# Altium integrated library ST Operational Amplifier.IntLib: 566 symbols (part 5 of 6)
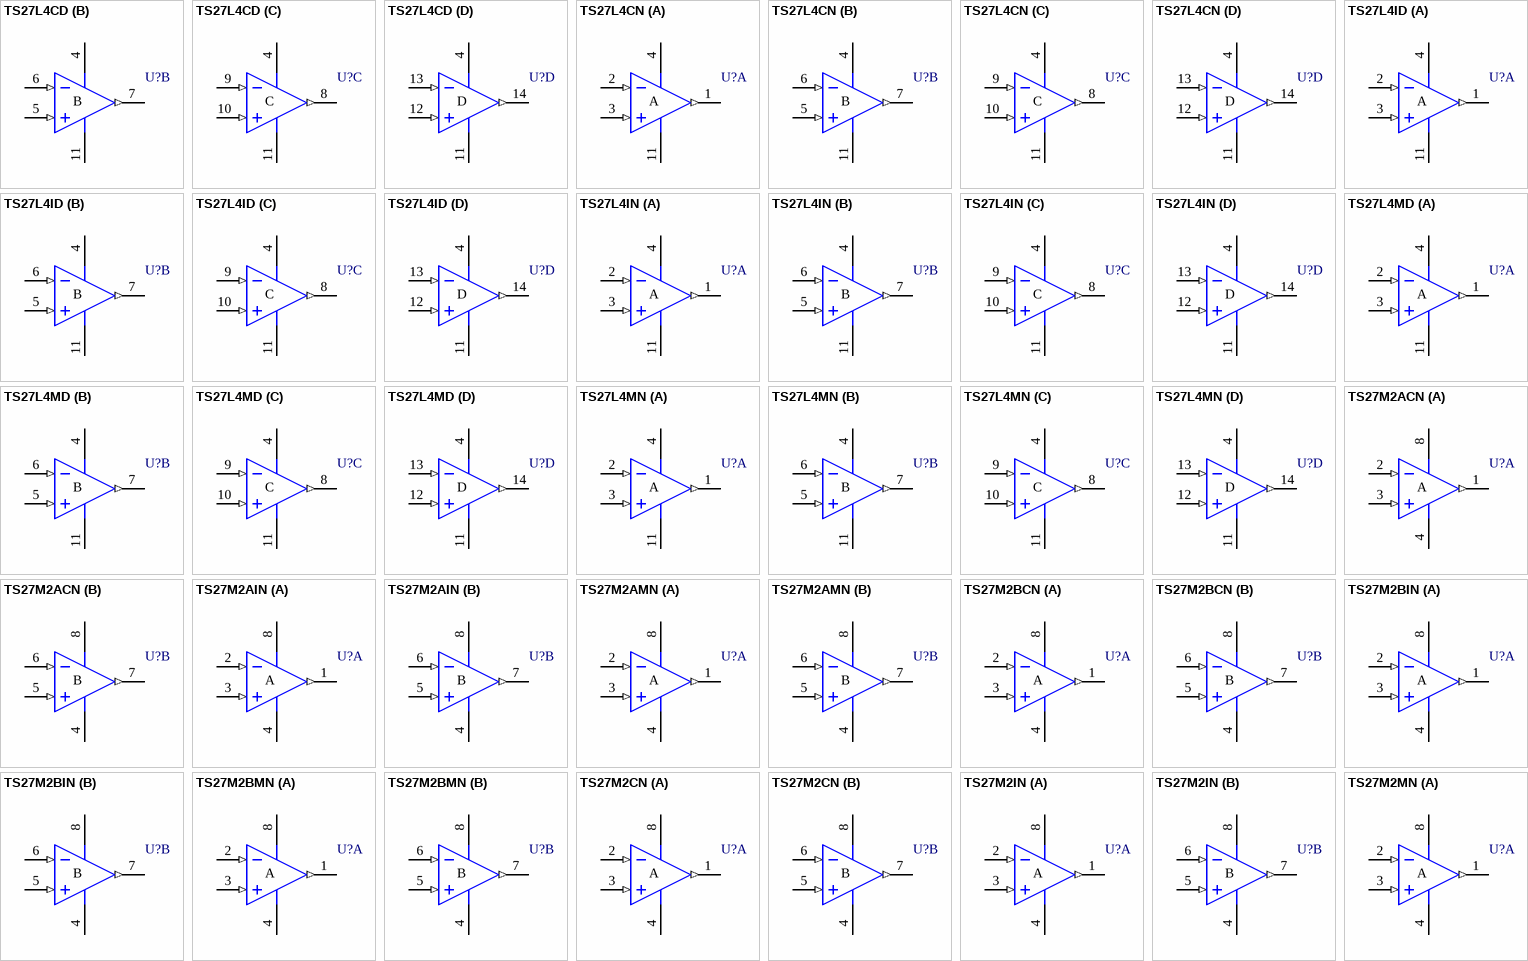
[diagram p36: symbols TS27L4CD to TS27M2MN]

## TS27L4ID
designator U?
Very Low-Power CMOS Quad Operational Amplifier
footprint SO14_N (SOIC, 14-Leads, Body 8.7x3.9mm, Pitch 1.27mm, IPC Medium Density)
footprint SO14_L (SOIC, 14-Leads, Body 8.7x3.9mm, Pitch 1.27mm, IPC High Density)
footprint SO14_M (SOIC, 14-Leads, Body 8.7x3.9mm, Pitch 1.27mm, IPC Low Density)
3D model SO14 (14-Pin Small Outline Integrated Circuit 1.27 mm Pitch)
pins on every part: 4 V+ (power), 11 V- (power)
part A pins: 1 OUT (out), 2 IN- (in), 3 IN+ (in)
part B pins: 5 IN+ (in), 6 IN- (in), 7 OUT (out)
part C pins: 8 OUT (out), 9 IN- (in), 10 IN+ (in)
part D pins: 12 IN+ (in), 13 IN- (in), 14 OUT (out)

## TS27L4IN
designator U?
Very Low-Power CMOS Quad Operational Amplifier
footprint DIP14 (DIP; 14 Leads; Row Spacing 7.62 mm; Pitch 2.54 mm)
3D model DIP14 (DIP; 14 Leads; Row Spacing 7.62 mm; Pitch 2.54 mm)
pins on every part: 4 V+ (power), 11 V- (power)
part A pins: 1 OUT (out), 2 IN- (in), 3 IN+ (in)
part B pins: 5 IN+ (in), 6 IN- (in), 7 OUT (out)
part C pins: 8 OUT (out), 9 IN- (in), 10 IN+ (in)
part D pins: 12 IN+ (in), 13 IN- (in), 14 OUT (out)

## TS27L4MD
designator U?
Very Low-Power CMOS Quad Operational Amplifier
footprint SO14_N (SOIC, 14-Leads, Body 8.7x3.9mm, Pitch 1.27mm, IPC Medium Density)
footprint SO14_L (SOIC, 14-Leads, Body 8.7x3.9mm, Pitch 1.27mm, IPC High Density)
footprint SO14_M (SOIC, 14-Leads, Body 8.7x3.9mm, Pitch 1.27mm, IPC Low Density)
3D model SO14 (14-Pin Small Outline Integrated Circuit 1.27 mm Pitch)
pins on every part: 4 V+ (power), 11 V- (power)
part A pins: 1 OUT (out), 2 IN- (in), 3 IN+ (in)
part B pins: 5 IN+ (in), 6 IN- (in), 7 OUT (out)
part C pins: 8 OUT (out), 9 IN- (in), 10 IN+ (in)
part D pins: 12 IN+ (in), 13 IN- (in), 14 OUT (out)

## TS27L4MN
designator U?
Very Low-Power CMOS Quad Operational Amplifier
footprint DIP14 (DIP; 14 Leads; Row Spacing 7.62 mm; Pitch 2.54 mm)
3D model DIP14 (DIP; 14 Leads; Row Spacing 7.62 mm; Pitch 2.54 mm)
pins on every part: 4 V+ (power), 11 V- (power)
part A pins: 1 OUT (out), 2 IN- (in), 3 IN+ (in)
part B pins: 5 IN+ (in), 6 IN- (in), 7 OUT (out)
part C pins: 8 OUT (out), 9 IN- (in), 10 IN+ (in)
part D pins: 12 IN+ (in), 13 IN- (in), 14 OUT (out)

## TS27M2ACN
designator U?
Low-Power CMOS Dual Operational Amplifier
footprint DIP8 (DIP; 8 Leads; Row Spacing 7.62 mm; Pitch 2.54 mm)
3D model DIP8 (DIP; 8 Leads; Row Spacing 7.62 mm; Pitch 2.54 mm)
pins on every part: 4 V- (power), 8 V+ (power)
part A pins: 1 OUT (out), 2 IN- (in), 3 IN+ (in)
part B pins: 5 IN+ (in), 6 IN- (in), 7 OUT (out)

## TS27M2AIN
designator U?
Low-Power CMOS Dual Operational Amplifier
footprint DIP8 (DIP; 8 Leads; Row Spacing 7.62 mm; Pitch 2.54 mm)
3D model DIP8 (DIP; 8 Leads; Row Spacing 7.62 mm; Pitch 2.54 mm)
pins on every part: 4 V- (power), 8 V+ (power)
part A pins: 1 OUT (out), 2 IN- (in), 3 IN+ (in)
part B pins: 5 IN+ (in), 6 IN- (in), 7 OUT (out)

## TS27M2AMN
designator U?
Low-Power CMOS Dual Operational Amplifier
footprint DIP8 (DIP; 8 Leads; Row Spacing 7.62 mm; Pitch 2.54 mm)
3D model DIP8 (DIP; 8 Leads; Row Spacing 7.62 mm; Pitch 2.54 mm)
pins on every part: 4 V- (power), 8 V+ (power)
part A pins: 1 OUT (out), 2 IN- (in), 3 IN+ (in)
part B pins: 5 IN+ (in), 6 IN- (in), 7 OUT (out)

## TS27M2BCN
designator U?
Low-Power CMOS Dual Operational Amplifier
footprint DIP8 (DIP; 8 Leads; Row Spacing 7.62 mm; Pitch 2.54 mm)
3D model DIP8 (DIP; 8 Leads; Row Spacing 7.62 mm; Pitch 2.54 mm)
pins on every part: 4 V- (power), 8 V+ (power)
part A pins: 1 OUT (out), 2 IN- (in), 3 IN+ (in)
part B pins: 5 IN+ (in), 6 IN- (in), 7 OUT (out)

## TS27M2BIN
designator U?
Low-Power CMOS Dual Operational Amplifier
footprint DIP8 (DIP; 8 Leads; Row Spacing 7.62 mm; Pitch 2.54 mm)
3D model DIP8 (DIP; 8 Leads; Row Spacing 7.62 mm; Pitch 2.54 mm)
pins on every part: 4 V- (power), 8 V+ (power)
part A pins: 1 OUT (out), 2 IN- (in), 3 IN+ (in)
part B pins: 5 IN+ (in), 6 IN- (in), 7 OUT (out)

## TS27M2BMN
designator U?
Low-Power CMOS Dual Operational Amplifier
footprint DIP8 (DIP; 8 Leads; Row Spacing 7.62 mm; Pitch 2.54 mm)
3D model DIP8 (DIP; 8 Leads; Row Spacing 7.62 mm; Pitch 2.54 mm)
pins on every part: 4 V- (power), 8 V+ (power)
part A pins: 1 OUT (out), 2 IN- (in), 3 IN+ (in)
part B pins: 5 IN+ (in), 6 IN- (in), 7 OUT (out)

## TS27M2CN
designator U?
Low-Power CMOS Dual Operational Amplifier
footprint DIP8 (DIP; 8 Leads; Row Spacing 7.62 mm; Pitch 2.54 mm)
3D model DIP8 (DIP; 8 Leads; Row Spacing 7.62 mm; Pitch 2.54 mm)
pins on every part: 4 V- (power), 8 V+ (power)
part A pins: 1 OUT (out), 2 IN- (in), 3 IN+ (in)
part B pins: 5 IN+ (in), 6 IN- (in), 7 OUT (out)

## TS27M2IN
designator U?
Low-Power CMOS Dual Operational Amplifier
footprint DIP8 (DIP; 8 Leads; Row Spacing 7.62 mm; Pitch 2.54 mm)
3D model DIP8 (DIP; 8 Leads; Row Spacing 7.62 mm; Pitch 2.54 mm)
pins on every part: 4 V- (power), 8 V+ (power)
part A pins: 1 OUT (out), 2 IN- (in), 3 IN+ (in)
part B pins: 5 IN+ (in), 6 IN- (in), 7 OUT (out)

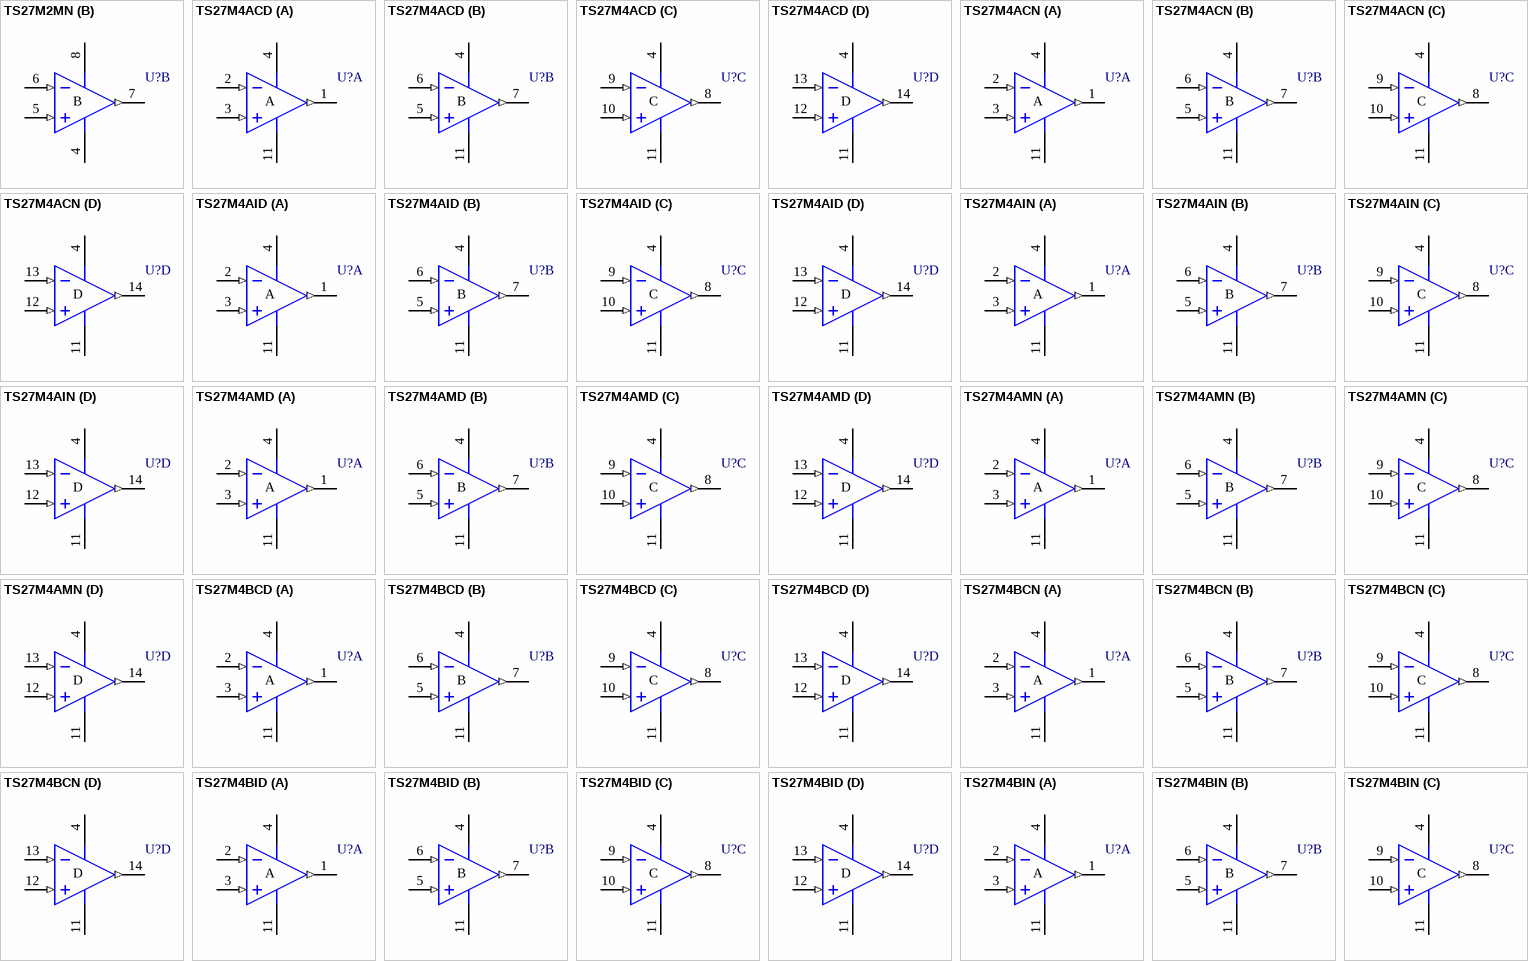
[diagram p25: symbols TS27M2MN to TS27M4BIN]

## TS27M2MN
designator U?
Low-Power CMOS Dual Operational Amplifier
footprint DIP8 (DIP; 8 Leads; Row Spacing 7.62 mm; Pitch 2.54 mm)
3D model DIP8 (DIP; 8 Leads; Row Spacing 7.62 mm; Pitch 2.54 mm)
pins on every part: 4 V- (power), 8 V+ (power)
part A pins: 1 OUT (out), 2 IN- (in), 3 IN+ (in)
part B pins: 5 IN+ (in), 6 IN- (in), 7 OUT (out)

## TS27M4ACD
designator U?
Low-Power CMOS Quad Operational Amplifier
footprint SO14_N (SOIC, 14-Leads, Body 8.7x3.9mm, Pitch 1.27mm, IPC Medium Density)
footprint SO14_L (SOIC, 14-Leads, Body 8.7x3.9mm, Pitch 1.27mm, IPC High Density)
footprint SO14_M (SOIC, 14-Leads, Body 8.7x3.9mm, Pitch 1.27mm, IPC Low Density)
3D model SO14 (14-Pin Small Outline Integrated Circuit 1.27 mm Pitch)
pins on every part: 4 V+ (power), 11 V- (power)
part A pins: 1 OUT (out), 2 IN- (in), 3 IN+ (in)
part B pins: 5 IN+ (in), 6 IN- (in), 7 OUT (out)
part C pins: 8 OUT (out), 9 IN- (in), 10 IN+ (in)
part D pins: 12 IN+ (in), 13 IN- (in), 14 OUT (out)

## TS27M4ACN
designator U?
Low-Power CMOS Quad Operational Amplifier
footprint DIP14 (DIP; 14 Leads; Row Spacing 7.62 mm; Pitch 2.54 mm)
3D model DIP14 (DIP; 14 Leads; Row Spacing 7.62 mm; Pitch 2.54 mm)
pins on every part: 4 V+ (power), 11 V- (power)
part A pins: 1 OUT (out), 2 IN- (in), 3 IN+ (in)
part B pins: 5 IN+ (in), 6 IN- (in), 7 OUT (out)
part C pins: 8 OUT (out), 9 IN- (in), 10 IN+ (in)
part D pins: 12 IN+ (in), 13 IN- (in), 14 OUT (out)

## TS27M4AID
designator U?
Low-Power CMOS Quad Operational Amplifier
footprint SO14_N (SOIC, 14-Leads, Body 8.7x3.9mm, Pitch 1.27mm, IPC Medium Density)
footprint SO14_L (SOIC, 14-Leads, Body 8.7x3.9mm, Pitch 1.27mm, IPC High Density)
footprint SO14_M (SOIC, 14-Leads, Body 8.7x3.9mm, Pitch 1.27mm, IPC Low Density)
3D model SO14 (14-Pin Small Outline Integrated Circuit 1.27 mm Pitch)
pins on every part: 4 V+ (power), 11 V- (power)
part A pins: 1 OUT (out), 2 IN- (in), 3 IN+ (in)
part B pins: 5 IN+ (in), 6 IN- (in), 7 OUT (out)
part C pins: 8 OUT (out), 9 IN- (in), 10 IN+ (in)
part D pins: 12 IN+ (in), 13 IN- (in), 14 OUT (out)

## TS27M4AIN
designator U?
Low-Power CMOS Quad Operational Amplifier
footprint DIP14 (DIP; 14 Leads; Row Spacing 7.62 mm; Pitch 2.54 mm)
3D model DIP14 (DIP; 14 Leads; Row Spacing 7.62 mm; Pitch 2.54 mm)
pins on every part: 4 V+ (power), 11 V- (power)
part A pins: 1 OUT (out), 2 IN- (in), 3 IN+ (in)
part B pins: 5 IN+ (in), 6 IN- (in), 7 OUT (out)
part C pins: 8 OUT (out), 9 IN- (in), 10 IN+ (in)
part D pins: 12 IN+ (in), 13 IN- (in), 14 OUT (out)

## TS27M4AMD
designator U?
Low-Power CMOS Quad Operational Amplifier
footprint SO14_N (SOIC, 14-Leads, Body 8.7x3.9mm, Pitch 1.27mm, IPC Medium Density)
footprint SO14_L (SOIC, 14-Leads, Body 8.7x3.9mm, Pitch 1.27mm, IPC High Density)
footprint SO14_M (SOIC, 14-Leads, Body 8.7x3.9mm, Pitch 1.27mm, IPC Low Density)
3D model SO14 (14-Pin Small Outline Integrated Circuit 1.27 mm Pitch)
pins on every part: 4 V+ (power), 11 V- (power)
part A pins: 1 OUT (out), 2 IN- (in), 3 IN+ (in)
part B pins: 5 IN+ (in), 6 IN- (in), 7 OUT (out)
part C pins: 8 OUT (out), 9 IN- (in), 10 IN+ (in)
part D pins: 12 IN+ (in), 13 IN- (in), 14 OUT (out)

## TS27M4AMN
designator U?
Low-Power CMOS Quad Operational Amplifier
footprint DIP14 (DIP; 14 Leads; Row Spacing 7.62 mm; Pitch 2.54 mm)
3D model DIP14 (DIP; 14 Leads; Row Spacing 7.62 mm; Pitch 2.54 mm)
pins on every part: 4 V+ (power), 11 V- (power)
part A pins: 1 OUT (out), 2 IN- (in), 3 IN+ (in)
part B pins: 5 IN+ (in), 6 IN- (in), 7 OUT (out)
part C pins: 8 OUT (out), 9 IN- (in), 10 IN+ (in)
part D pins: 12 IN+ (in), 13 IN- (in), 14 OUT (out)

## TS27M4BCD
designator U?
Low-Power CMOS Quad Operational Amplifier
footprint SO14_N (SOIC, 14-Leads, Body 8.7x3.9mm, Pitch 1.27mm, IPC Medium Density)
footprint SO14_L (SOIC, 14-Leads, Body 8.7x3.9mm, Pitch 1.27mm, IPC High Density)
footprint SO14_M (SOIC, 14-Leads, Body 8.7x3.9mm, Pitch 1.27mm, IPC Low Density)
3D model SO14 (14-Pin Small Outline Integrated Circuit 1.27 mm Pitch)
pins on every part: 4 V+ (power), 11 V- (power)
part A pins: 1 OUT (out), 2 IN- (in), 3 IN+ (in)
part B pins: 5 IN+ (in), 6 IN- (in), 7 OUT (out)
part C pins: 8 OUT (out), 9 IN- (in), 10 IN+ (in)
part D pins: 12 IN+ (in), 13 IN- (in), 14 OUT (out)

## TS27M4BCN
designator U?
Low-Power CMOS Quad Operational Amplifier
footprint DIP14 (DIP; 14 Leads; Row Spacing 7.62 mm; Pitch 2.54 mm)
3D model DIP14 (DIP; 14 Leads; Row Spacing 7.62 mm; Pitch 2.54 mm)
pins on every part: 4 V+ (power), 11 V- (power)
part A pins: 1 OUT (out), 2 IN- (in), 3 IN+ (in)
part B pins: 5 IN+ (in), 6 IN- (in), 7 OUT (out)
part C pins: 8 OUT (out), 9 IN- (in), 10 IN+ (in)
part D pins: 12 IN+ (in), 13 IN- (in), 14 OUT (out)

## TS27M4BID
designator U?
Low-Power CMOS Quad Operational Amplifier
footprint SO14_N (SOIC, 14-Leads, Body 8.7x3.9mm, Pitch 1.27mm, IPC Medium Density)
footprint SO14_L (SOIC, 14-Leads, Body 8.7x3.9mm, Pitch 1.27mm, IPC High Density)
footprint SO14_M (SOIC, 14-Leads, Body 8.7x3.9mm, Pitch 1.27mm, IPC Low Density)
3D model SO14 (14-Pin Small Outline Integrated Circuit 1.27 mm Pitch)
pins on every part: 4 V+ (power), 11 V- (power)
part A pins: 1 OUT (out), 2 IN- (in), 3 IN+ (in)
part B pins: 5 IN+ (in), 6 IN- (in), 7 OUT (out)
part C pins: 8 OUT (out), 9 IN- (in), 10 IN+ (in)
part D pins: 12 IN+ (in), 13 IN- (in), 14 OUT (out)

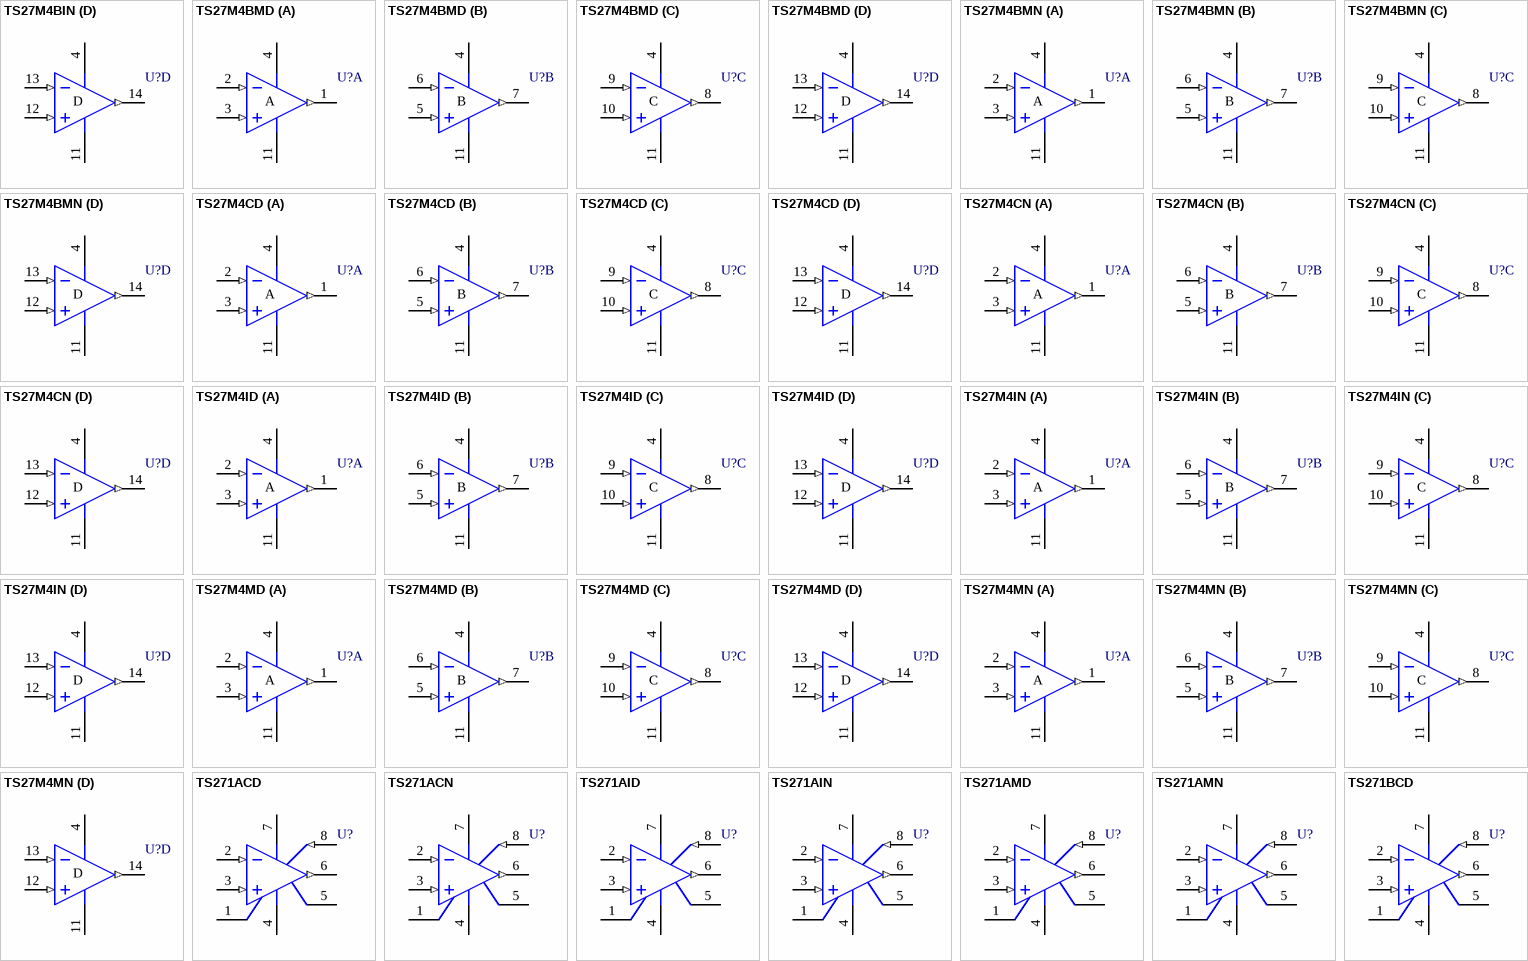
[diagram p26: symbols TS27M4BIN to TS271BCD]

## TS27M4BIN
designator U?
Low-Power CMOS Quad Operational Amplifier
footprint DIP14 (DIP; 14 Leads; Row Spacing 7.62 mm; Pitch 2.54 mm)
3D model DIP14 (DIP; 14 Leads; Row Spacing 7.62 mm; Pitch 2.54 mm)
pins on every part: 4 V+ (power), 11 V- (power)
part A pins: 1 OUT (out), 2 IN- (in), 3 IN+ (in)
part B pins: 5 IN+ (in), 6 IN- (in), 7 OUT (out)
part C pins: 8 OUT (out), 9 IN- (in), 10 IN+ (in)
part D pins: 12 IN+ (in), 13 IN- (in), 14 OUT (out)

## TS27M4BMD
designator U?
Low-Power CMOS Quad Operational Amplifier
footprint SO14_N (SOIC, 14-Leads, Body 8.7x3.9mm, Pitch 1.27mm, IPC Medium Density)
footprint SO14_L (SOIC, 14-Leads, Body 8.7x3.9mm, Pitch 1.27mm, IPC High Density)
footprint SO14_M (SOIC, 14-Leads, Body 8.7x3.9mm, Pitch 1.27mm, IPC Low Density)
3D model SO14 (14-Pin Small Outline Integrated Circuit 1.27 mm Pitch)
pins on every part: 4 V+ (power), 11 V- (power)
part A pins: 1 OUT (out), 2 IN- (in), 3 IN+ (in)
part B pins: 5 IN+ (in), 6 IN- (in), 7 OUT (out)
part C pins: 8 OUT (out), 9 IN- (in), 10 IN+ (in)
part D pins: 12 IN+ (in), 13 IN- (in), 14 OUT (out)

## TS27M4BMN
designator U?
Low-Power CMOS Quad Operational Amplifier
footprint DIP14 (DIP; 14 Leads; Row Spacing 7.62 mm; Pitch 2.54 mm)
3D model DIP14 (DIP; 14 Leads; Row Spacing 7.62 mm; Pitch 2.54 mm)
pins on every part: 4 V+ (power), 11 V- (power)
part A pins: 1 OUT (out), 2 IN- (in), 3 IN+ (in)
part B pins: 5 IN+ (in), 6 IN- (in), 7 OUT (out)
part C pins: 8 OUT (out), 9 IN- (in), 10 IN+ (in)
part D pins: 12 IN+ (in), 13 IN- (in), 14 OUT (out)

## TS27M4CD
designator U?
Low-Power CMOS Quad Operational Amplifier
footprint SO14_N (SOIC, 14-Leads, Body 8.7x3.9mm, Pitch 1.27mm, IPC Medium Density)
footprint SO14_L (SOIC, 14-Leads, Body 8.7x3.9mm, Pitch 1.27mm, IPC High Density)
footprint SO14_M (SOIC, 14-Leads, Body 8.7x3.9mm, Pitch 1.27mm, IPC Low Density)
3D model SO14 (14-Pin Small Outline Integrated Circuit 1.27 mm Pitch)
pins on every part: 4 V+ (power), 11 V- (power)
part A pins: 1 OUT (out), 2 IN- (in), 3 IN+ (in)
part B pins: 5 IN+ (in), 6 IN- (in), 7 OUT (out)
part C pins: 8 OUT (out), 9 IN- (in), 10 IN+ (in)
part D pins: 12 IN+ (in), 13 IN- (in), 14 OUT (out)

## TS27M4CN
designator U?
Low-Power CMOS Quad Operational Amplifier
footprint DIP14 (DIP; 14 Leads; Row Spacing 7.62 mm; Pitch 2.54 mm)
3D model DIP14 (DIP; 14 Leads; Row Spacing 7.62 mm; Pitch 2.54 mm)
pins on every part: 4 V+ (power), 11 V- (power)
part A pins: 1 OUT (out), 2 IN- (in), 3 IN+ (in)
part B pins: 5 IN+ (in), 6 IN- (in), 7 OUT (out)
part C pins: 8 OUT (out), 9 IN- (in), 10 IN+ (in)
part D pins: 12 IN+ (in), 13 IN- (in), 14 OUT (out)

## TS27M4ID
designator U?
Low-Power CMOS Quad Operational Amplifier
footprint SO14_N (SOIC, 14-Leads, Body 8.7x3.9mm, Pitch 1.27mm, IPC Medium Density)
footprint SO14_L (SOIC, 14-Leads, Body 8.7x3.9mm, Pitch 1.27mm, IPC High Density)
footprint SO14_M (SOIC, 14-Leads, Body 8.7x3.9mm, Pitch 1.27mm, IPC Low Density)
3D model SO14 (14-Pin Small Outline Integrated Circuit 1.27 mm Pitch)
pins on every part: 4 V+ (power), 11 V- (power)
part A pins: 1 OUT (out), 2 IN- (in), 3 IN+ (in)
part B pins: 5 IN+ (in), 6 IN- (in), 7 OUT (out)
part C pins: 8 OUT (out), 9 IN- (in), 10 IN+ (in)
part D pins: 12 IN+ (in), 13 IN- (in), 14 OUT (out)

## TS27M4IN
designator U?
Low-Power CMOS Quad Operational Amplifier
footprint DIP14 (DIP; 14 Leads; Row Spacing 7.62 mm; Pitch 2.54 mm)
3D model DIP14 (DIP; 14 Leads; Row Spacing 7.62 mm; Pitch 2.54 mm)
pins on every part: 4 V+ (power), 11 V- (power)
part A pins: 1 OUT (out), 2 IN- (in), 3 IN+ (in)
part B pins: 5 IN+ (in), 6 IN- (in), 7 OUT (out)
part C pins: 8 OUT (out), 9 IN- (in), 10 IN+ (in)
part D pins: 12 IN+ (in), 13 IN- (in), 14 OUT (out)

## TS27M4MD
designator U?
Low-Power CMOS Quad Operational Amplifier
footprint SO14_N (SOIC, 14-Leads, Body 8.7x3.9mm, Pitch 1.27mm, IPC Medium Density)
footprint SO14_L (SOIC, 14-Leads, Body 8.7x3.9mm, Pitch 1.27mm, IPC High Density)
footprint SO14_M (SOIC, 14-Leads, Body 8.7x3.9mm, Pitch 1.27mm, IPC Low Density)
3D model SO14 (14-Pin Small Outline Integrated Circuit 1.27 mm Pitch)
pins on every part: 4 V+ (power), 11 V- (power)
part A pins: 1 OUT (out), 2 IN- (in), 3 IN+ (in)
part B pins: 5 IN+ (in), 6 IN- (in), 7 OUT (out)
part C pins: 8 OUT (out), 9 IN- (in), 10 IN+ (in)
part D pins: 12 IN+ (in), 13 IN- (in), 14 OUT (out)

## TS27M4MN
designator U?
Low-Power CMOS Quad Operational Amplifier
footprint DIP14 (DIP; 14 Leads; Row Spacing 7.62 mm; Pitch 2.54 mm)
3D model DIP14 (DIP; 14 Leads; Row Spacing 7.62 mm; Pitch 2.54 mm)
pins on every part: 4 V+ (power), 11 V- (power)
part A pins: 1 OUT (out), 2 IN- (in), 3 IN+ (in)
part B pins: 5 IN+ (in), 6 IN- (in), 7 OUT (out)
part C pins: 8 OUT (out), 9 IN- (in), 10 IN+ (in)
part D pins: 12 IN+ (in), 13 IN- (in), 14 OUT (out)

## TS271ACD
designator U?
Programmable CMOS Single Operational Amplifier
footprint SO8_N (SOIC, 8-Leads, Body 4.9x3.9mm, Pitch 1.27mm, IPC Medium Density)
footprint SO8_L (SOIC, 8-Leads, Body 4.9x3.9mm, Pitch 1.27mm, IPC High Density)
footprint SO8_M (SOIC, 8-Leads, Body 4.9x3.9mm, Pitch 1.27mm, IPC Low Density)
3D model SO8 (8-Pin Small Outline Integrated Circuit 1.27 mm Pitch)
pins: 1 OS NULL1, 2 IN- (in), 3 IN+ (in), 4 V- (power), 5 OS NULL2, 6 OUT (out), 7 V+ (power), 8 ISET (in)

## TS271ACN
designator U?
Programmable CMOS Single Operational Amplifier
footprint DIP8 (DIP; 8 Leads; Row Spacing 7.62 mm; Pitch 2.54 mm)
3D model DIP8 (DIP; 8 Leads; Row Spacing 7.62 mm; Pitch 2.54 mm)
pins: 1 OS NULL1, 2 IN- (in), 3 IN+ (in), 4 V- (power), 5 OS NULL2, 6 OUT (out), 7 V+ (power), 8 ISET (in)

## TS271AID
designator U?
Programmable CMOS Single Operational Amplifier
footprint SO8_N (SOIC, 8-Leads, Body 4.9x3.9mm, Pitch 1.27mm, IPC Medium Density)
footprint SO8_L (SOIC, 8-Leads, Body 4.9x3.9mm, Pitch 1.27mm, IPC High Density)
footprint SO8_M (SOIC, 8-Leads, Body 4.9x3.9mm, Pitch 1.27mm, IPC Low Density)
3D model SO8 (8-Pin Small Outline Integrated Circuit 1.27 mm Pitch)
pins: 1 OS NULL1, 2 IN- (in), 3 IN+ (in), 4 V- (power), 5 OS NULL2, 6 OUT (out), 7 V+ (power), 8 ISET (in)

## TS271AIN
designator U?
Programmable CMOS Single Operational Amplifier
footprint DIP8 (DIP; 8 Leads; Row Spacing 7.62 mm; Pitch 2.54 mm)
3D model DIP8 (DIP; 8 Leads; Row Spacing 7.62 mm; Pitch 2.54 mm)
pins: 1 OS NULL1, 2 IN- (in), 3 IN+ (in), 4 V- (power), 5 OS NULL2, 6 OUT (out), 7 V+ (power), 8 ISET (in)

## TS271AMD
designator U?
Programmable CMOS Single Operational Amplifier
footprint SO8_N (SOIC, 8-Leads, Body 4.9x3.9mm, Pitch 1.27mm, IPC Medium Density)
footprint SO8_L (SOIC, 8-Leads, Body 4.9x3.9mm, Pitch 1.27mm, IPC High Density)
footprint SO8_M (SOIC, 8-Leads, Body 4.9x3.9mm, Pitch 1.27mm, IPC Low Density)
3D model SO8 (8-Pin Small Outline Integrated Circuit 1.27 mm Pitch)
pins: 1 OS NULL1, 2 IN- (in), 3 IN+ (in), 4 V- (power), 5 OS NULL2, 6 OUT (out), 7 V+ (power), 8 ISET (in)

## TS271AMN
designator U?
Programmable CMOS Single Operational Amplifier
footprint DIP8 (DIP; 8 Leads; Row Spacing 7.62 mm; Pitch 2.54 mm)
3D model DIP8 (DIP; 8 Leads; Row Spacing 7.62 mm; Pitch 2.54 mm)
pins: 1 OS NULL1, 2 IN- (in), 3 IN+ (in), 4 V- (power), 5 OS NULL2, 6 OUT (out), 7 V+ (power), 8 ISET (in)

## TS271BCD
designator U?
Programmable CMOS Single Operational Amplifier
footprint SO8_N (SOIC, 8-Leads, Body 4.9x3.9mm, Pitch 1.27mm, IPC Medium Density)
footprint SO8_L (SOIC, 8-Leads, Body 4.9x3.9mm, Pitch 1.27mm, IPC High Density)
footprint SO8_M (SOIC, 8-Leads, Body 4.9x3.9mm, Pitch 1.27mm, IPC Low Density)
3D model SO8 (8-Pin Small Outline Integrated Circuit 1.27 mm Pitch)
pins: 1 OS NULL1, 2 IN- (in), 3 IN+ (in), 4 V- (power), 5 OS NULL2, 6 OUT (out), 7 V+ (power), 8 ISET (in)

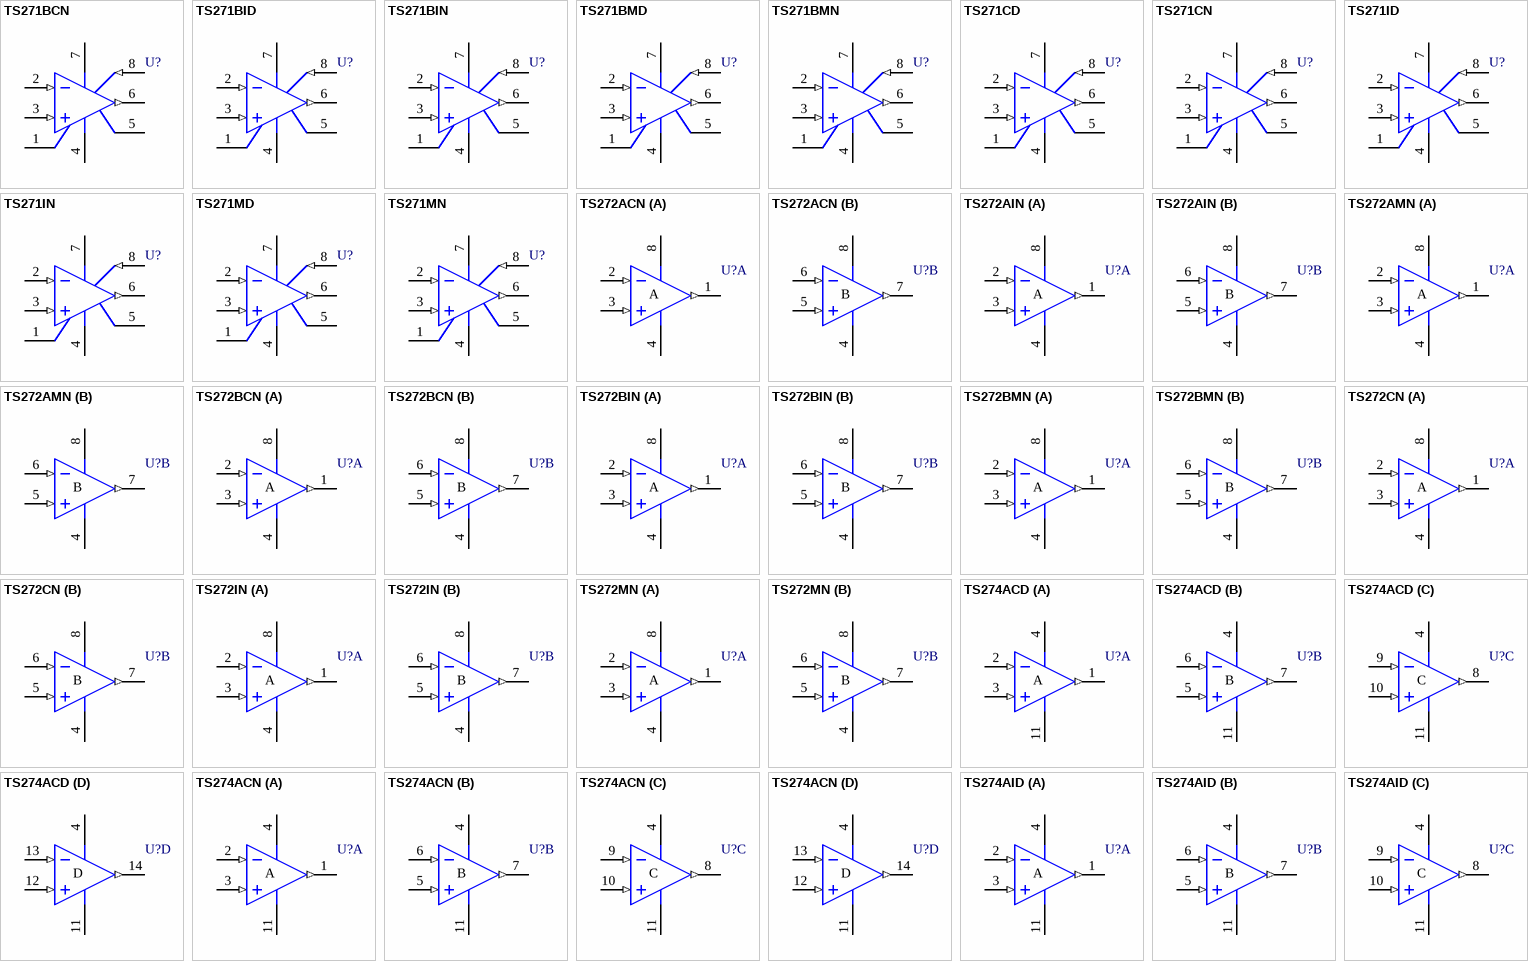
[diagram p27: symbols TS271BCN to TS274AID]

## TS271BCN
designator U?
Programmable CMOS Single Operational Amplifier
footprint DIP8 (DIP; 8 Leads; Row Spacing 7.62 mm; Pitch 2.54 mm)
3D model DIP8 (DIP; 8 Leads; Row Spacing 7.62 mm; Pitch 2.54 mm)
pins: 1 OS NULL1, 2 IN- (in), 3 IN+ (in), 4 V- (power), 5 OS NULL2, 6 OUT (out), 7 V+ (power), 8 ISET (in)

## TS271BID
designator U?
Programmable CMOS Single Operational Amplifier
footprint SO8_N (SOIC, 8-Leads, Body 4.9x3.9mm, Pitch 1.27mm, IPC Medium Density)
footprint SO8_L (SOIC, 8-Leads, Body 4.9x3.9mm, Pitch 1.27mm, IPC High Density)
footprint SO8_M (SOIC, 8-Leads, Body 4.9x3.9mm, Pitch 1.27mm, IPC Low Density)
3D model SO8 (8-Pin Small Outline Integrated Circuit 1.27 mm Pitch)
pins: 1 OS NULL1, 2 IN- (in), 3 IN+ (in), 4 V- (power), 5 OS NULL2, 6 OUT (out), 7 V+ (power), 8 ISET (in)

## TS271BIN
designator U?
Programmable CMOS Single Operational Amplifier
footprint DIP8 (DIP; 8 Leads; Row Spacing 7.62 mm; Pitch 2.54 mm)
3D model DIP8 (DIP; 8 Leads; Row Spacing 7.62 mm; Pitch 2.54 mm)
pins: 1 OS NULL1, 2 IN- (in), 3 IN+ (in), 4 V- (power), 5 OS NULL2, 6 OUT (out), 7 V+ (power), 8 ISET (in)

## TS271BMD
designator U?
Programmable CMOS Single Operational Amplifier
footprint SO8_N (SOIC, 8-Leads, Body 4.9x3.9mm, Pitch 1.27mm, IPC Medium Density)
footprint SO8_L (SOIC, 8-Leads, Body 4.9x3.9mm, Pitch 1.27mm, IPC High Density)
footprint SO8_M (SOIC, 8-Leads, Body 4.9x3.9mm, Pitch 1.27mm, IPC Low Density)
3D model SO8 (8-Pin Small Outline Integrated Circuit 1.27 mm Pitch)
pins: 1 OS NULL1, 2 IN- (in), 3 IN+ (in), 4 V- (power), 5 OS NULL2, 6 OUT (out), 7 V+ (power), 8 ISET (in)

## TS271BMN
designator U?
Programmable CMOS Single Operational Amplifier
footprint DIP8 (DIP; 8 Leads; Row Spacing 7.62 mm; Pitch 2.54 mm)
3D model DIP8 (DIP; 8 Leads; Row Spacing 7.62 mm; Pitch 2.54 mm)
pins: 1 OS NULL1, 2 IN- (in), 3 IN+ (in), 4 V- (power), 5 OS NULL2, 6 OUT (out), 7 V+ (power), 8 ISET (in)

## TS271CD
designator U?
Programmable CMOS Single Operational Amplifier
footprint SO8_N (SOIC, 8-Leads, Body 4.9x3.9mm, Pitch 1.27mm, IPC Medium Density)
footprint SO8_L (SOIC, 8-Leads, Body 4.9x3.9mm, Pitch 1.27mm, IPC High Density)
footprint SO8_M (SOIC, 8-Leads, Body 4.9x3.9mm, Pitch 1.27mm, IPC Low Density)
3D model SO8 (8-Pin Small Outline Integrated Circuit 1.27 mm Pitch)
pins: 1 OS NULL1, 2 IN- (in), 3 IN+ (in), 4 V- (power), 5 OS NULL2, 6 OUT (out), 7 V+ (power), 8 ISET (in)

## TS271CN
designator U?
Programmable CMOS Single Operational Amplifier
footprint DIP8 (DIP; 8 Leads; Row Spacing 7.62 mm; Pitch 2.54 mm)
3D model DIP8 (DIP; 8 Leads; Row Spacing 7.62 mm; Pitch 2.54 mm)
pins: 1 OS NULL1, 2 IN- (in), 3 IN+ (in), 4 V- (power), 5 OS NULL2, 6 OUT (out), 7 V+ (power), 8 ISET (in)

## TS271ID
designator U?
Programmable CMOS Single Operational Amplifier
footprint SO8_N (SOIC, 8-Leads, Body 4.9x3.9mm, Pitch 1.27mm, IPC Medium Density)
footprint SO8_L (SOIC, 8-Leads, Body 4.9x3.9mm, Pitch 1.27mm, IPC High Density)
footprint SO8_M (SOIC, 8-Leads, Body 4.9x3.9mm, Pitch 1.27mm, IPC Low Density)
3D model SO8 (8-Pin Small Outline Integrated Circuit 1.27 mm Pitch)
pins: 1 OS NULL1, 2 IN- (in), 3 IN+ (in), 4 V- (power), 5 OS NULL2, 6 OUT (out), 7 V+ (power), 8 ISET (in)

## TS271IN
designator U?
Programmable CMOS Single Operational Amplifier
footprint DIP8 (DIP; 8 Leads; Row Spacing 7.62 mm; Pitch 2.54 mm)
3D model DIP8 (DIP; 8 Leads; Row Spacing 7.62 mm; Pitch 2.54 mm)
pins: 1 OS NULL1, 2 IN- (in), 3 IN+ (in), 4 V- (power), 5 OS NULL2, 6 OUT (out), 7 V+ (power), 8 ISET (in)

## TS271MD
designator U?
Programmable CMOS Single Operational Amplifier
footprint SO8_N (SOIC, 8-Leads, Body 4.9x3.9mm, Pitch 1.27mm, IPC Medium Density)
footprint SO8_L (SOIC, 8-Leads, Body 4.9x3.9mm, Pitch 1.27mm, IPC High Density)
footprint SO8_M (SOIC, 8-Leads, Body 4.9x3.9mm, Pitch 1.27mm, IPC Low Density)
3D model SO8 (8-Pin Small Outline Integrated Circuit 1.27 mm Pitch)
pins: 1 OS NULL1, 2 IN- (in), 3 IN+ (in), 4 V- (power), 5 OS NULL2, 6 OUT (out), 7 V+ (power), 8 ISET (in)

## TS271MN
designator U?
Programmable CMOS Single Operational Amplifier
footprint DIP8 (DIP; 8 Leads; Row Spacing 7.62 mm; Pitch 2.54 mm)
3D model DIP8 (DIP; 8 Leads; Row Spacing 7.62 mm; Pitch 2.54 mm)
pins: 1 OS NULL1, 2 IN- (in), 3 IN+ (in), 4 V- (power), 5 OS NULL2, 6 OUT (out), 7 V+ (power), 8 ISET (in)

## TS272ACN
designator U?
High-Speed CMOS Dual Operational Amplifier
footprint DIP8 (DIP; 8 Leads; Row Spacing 7.62 mm; Pitch 2.54 mm)
3D model DIP8 (DIP; 8 Leads; Row Spacing 7.62 mm; Pitch 2.54 mm)
pins on every part: 4 V- (power), 8 V+ (power)
part A pins: 1 OUT (out), 2 IN- (in), 3 IN+ (in)
part B pins: 5 IN+ (in), 6 IN- (in), 7 OUT (out)

## TS272AIN
designator U?
High-Speed CMOS Dual Operational Amplifier
footprint DIP8 (DIP; 8 Leads; Row Spacing 7.62 mm; Pitch 2.54 mm)
3D model DIP8 (DIP; 8 Leads; Row Spacing 7.62 mm; Pitch 2.54 mm)
pins on every part: 4 V- (power), 8 V+ (power)
part A pins: 1 OUT (out), 2 IN- (in), 3 IN+ (in)
part B pins: 5 IN+ (in), 6 IN- (in), 7 OUT (out)

## TS272AMN
designator U?
High-Speed CMOS Dual Operational Amplifier
footprint DIP8 (DIP; 8 Leads; Row Spacing 7.62 mm; Pitch 2.54 mm)
3D model DIP8 (DIP; 8 Leads; Row Spacing 7.62 mm; Pitch 2.54 mm)
pins on every part: 4 V- (power), 8 V+ (power)
part A pins: 1 OUT (out), 2 IN- (in), 3 IN+ (in)
part B pins: 5 IN+ (in), 6 IN- (in), 7 OUT (out)

## TS272BCN
designator U?
High-Speed CMOS Dual Operational Amplifier
footprint DIP8 (DIP; 8 Leads; Row Spacing 7.62 mm; Pitch 2.54 mm)
3D model DIP8 (DIP; 8 Leads; Row Spacing 7.62 mm; Pitch 2.54 mm)
pins on every part: 4 V- (power), 8 V+ (power)
part A pins: 1 OUT (out), 2 IN- (in), 3 IN+ (in)
part B pins: 5 IN+ (in), 6 IN- (in), 7 OUT (out)

## TS272BIN
designator U?
High-Speed CMOS Dual Operational Amplifier
footprint DIP8 (DIP; 8 Leads; Row Spacing 7.62 mm; Pitch 2.54 mm)
3D model DIP8 (DIP; 8 Leads; Row Spacing 7.62 mm; Pitch 2.54 mm)
pins on every part: 4 V- (power), 8 V+ (power)
part A pins: 1 OUT (out), 2 IN- (in), 3 IN+ (in)
part B pins: 5 IN+ (in), 6 IN- (in), 7 OUT (out)

## TS272BMN
designator U?
High-Speed CMOS Dual Operational Amplifier
footprint DIP8 (DIP; 8 Leads; Row Spacing 7.62 mm; Pitch 2.54 mm)
3D model DIP8 (DIP; 8 Leads; Row Spacing 7.62 mm; Pitch 2.54 mm)
pins on every part: 4 V- (power), 8 V+ (power)
part A pins: 1 OUT (out), 2 IN- (in), 3 IN+ (in)
part B pins: 5 IN+ (in), 6 IN- (in), 7 OUT (out)

## TS272CN
designator U?
High-Speed CMOS Dual Operational Amplifier
footprint DIP8 (DIP; 8 Leads; Row Spacing 7.62 mm; Pitch 2.54 mm)
3D model DIP8 (DIP; 8 Leads; Row Spacing 7.62 mm; Pitch 2.54 mm)
pins on every part: 4 V- (power), 8 V+ (power)
part A pins: 1 OUT (out), 2 IN- (in), 3 IN+ (in)
part B pins: 5 IN+ (in), 6 IN- (in), 7 OUT (out)

## TS272IN
designator U?
High-Speed CMOS Dual Operational Amplifier
footprint DIP8 (DIP; 8 Leads; Row Spacing 7.62 mm; Pitch 2.54 mm)
3D model DIP8 (DIP; 8 Leads; Row Spacing 7.62 mm; Pitch 2.54 mm)
pins on every part: 4 V- (power), 8 V+ (power)
part A pins: 1 OUT (out), 2 IN- (in), 3 IN+ (in)
part B pins: 5 IN+ (in), 6 IN- (in), 7 OUT (out)

## TS272MN
designator U?
High-Speed CMOS Dual Operational Amplifier
footprint DIP8 (DIP; 8 Leads; Row Spacing 7.62 mm; Pitch 2.54 mm)
3D model DIP8 (DIP; 8 Leads; Row Spacing 7.62 mm; Pitch 2.54 mm)
pins on every part: 4 V- (power), 8 V+ (power)
part A pins: 1 OUT (out), 2 IN- (in), 3 IN+ (in)
part B pins: 5 IN+ (in), 6 IN- (in), 7 OUT (out)

## TS274ACD
designator U?
High-Speed CMOS Quad Operational Amplifier
footprint SO14_N (SOIC, 14-Leads, Body 8.7x3.9mm, Pitch 1.27mm, IPC Medium Density)
footprint SO14_L (SOIC, 14-Leads, Body 8.7x3.9mm, Pitch 1.27mm, IPC High Density)
footprint SO14_M (SOIC, 14-Leads, Body 8.7x3.9mm, Pitch 1.27mm, IPC Low Density)
3D model SO14 (14-Pin Small Outline Integrated Circuit 1.27 mm Pitch)
pins on every part: 4 V+ (power), 11 V- (power)
part A pins: 1 OUT (out), 2 IN- (in), 3 IN+ (in)
part B pins: 5 IN+ (in), 6 IN- (in), 7 OUT (out)
part C pins: 8 OUT (out), 9 IN- (in), 10 IN+ (in)
part D pins: 12 IN+ (in), 13 IN- (in), 14 OUT (out)

## TS274ACN
designator U?
High-Speed CMOS Quad Operational Amplifier
footprint DIP14 (DIP; 14 Leads; Row Spacing 7.62 mm; Pitch 2.54 mm)
3D model DIP14 (DIP; 14 Leads; Row Spacing 7.62 mm; Pitch 2.54 mm)
pins on every part: 4 V+ (power), 11 V- (power)
part A pins: 1 OUT (out), 2 IN- (in), 3 IN+ (in)
part B pins: 5 IN+ (in), 6 IN- (in), 7 OUT (out)
part C pins: 8 OUT (out), 9 IN- (in), 10 IN+ (in)
part D pins: 12 IN+ (in), 13 IN- (in), 14 OUT (out)

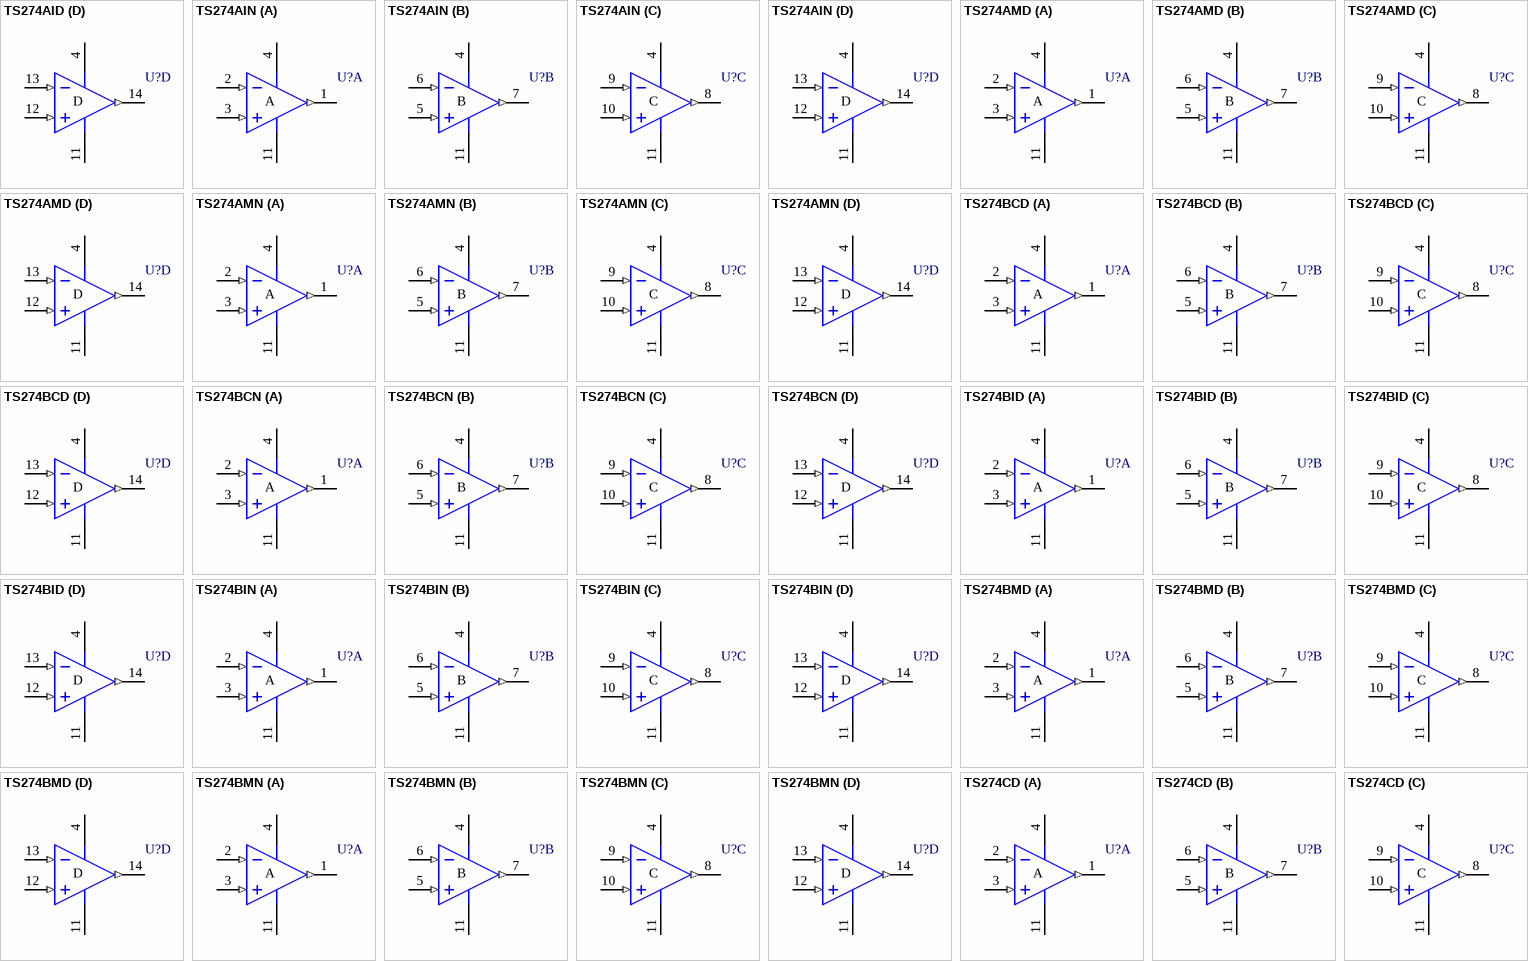
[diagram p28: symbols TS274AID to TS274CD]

## TS274AID
designator U?
High-Speed CMOS Quad Operational Amplifier
footprint SO14_N (SOIC, 14-Leads, Body 8.7x3.9mm, Pitch 1.27mm, IPC Medium Density)
footprint SO14_L (SOIC, 14-Leads, Body 8.7x3.9mm, Pitch 1.27mm, IPC High Density)
footprint SO14_M (SOIC, 14-Leads, Body 8.7x3.9mm, Pitch 1.27mm, IPC Low Density)
3D model SO14 (14-Pin Small Outline Integrated Circuit 1.27 mm Pitch)
pins on every part: 4 V+ (power), 11 V- (power)
part A pins: 1 OUT (out), 2 IN- (in), 3 IN+ (in)
part B pins: 5 IN+ (in), 6 IN- (in), 7 OUT (out)
part C pins: 8 OUT (out), 9 IN- (in), 10 IN+ (in)
part D pins: 12 IN+ (in), 13 IN- (in), 14 OUT (out)

## TS274AIN
designator U?
High-Speed CMOS Quad Operational Amplifier
footprint DIP14 (DIP; 14 Leads; Row Spacing 7.62 mm; Pitch 2.54 mm)
3D model DIP14 (DIP; 14 Leads; Row Spacing 7.62 mm; Pitch 2.54 mm)
pins on every part: 4 V+ (power), 11 V- (power)
part A pins: 1 OUT (out), 2 IN- (in), 3 IN+ (in)
part B pins: 5 IN+ (in), 6 IN- (in), 7 OUT (out)
part C pins: 8 OUT (out), 9 IN- (in), 10 IN+ (in)
part D pins: 12 IN+ (in), 13 IN- (in), 14 OUT (out)

## TS274AMD
designator U?
High-Speed CMOS Quad Operational Amplifier
footprint SO14_N (SOIC, 14-Leads, Body 8.7x3.9mm, Pitch 1.27mm, IPC Medium Density)
footprint SO14_L (SOIC, 14-Leads, Body 8.7x3.9mm, Pitch 1.27mm, IPC High Density)
footprint SO14_M (SOIC, 14-Leads, Body 8.7x3.9mm, Pitch 1.27mm, IPC Low Density)
3D model SO14 (14-Pin Small Outline Integrated Circuit 1.27 mm Pitch)
pins on every part: 4 V+ (power), 11 V- (power)
part A pins: 1 OUT (out), 2 IN- (in), 3 IN+ (in)
part B pins: 5 IN+ (in), 6 IN- (in), 7 OUT (out)
part C pins: 8 OUT (out), 9 IN- (in), 10 IN+ (in)
part D pins: 12 IN+ (in), 13 IN- (in), 14 OUT (out)

## TS274AMN
designator U?
High-Speed CMOS Quad Operational Amplifier
footprint DIP14 (DIP; 14 Leads; Row Spacing 7.62 mm; Pitch 2.54 mm)
3D model DIP14 (DIP; 14 Leads; Row Spacing 7.62 mm; Pitch 2.54 mm)
pins on every part: 4 V+ (power), 11 V- (power)
part A pins: 1 OUT (out), 2 IN- (in), 3 IN+ (in)
part B pins: 5 IN+ (in), 6 IN- (in), 7 OUT (out)
part C pins: 8 OUT (out), 9 IN- (in), 10 IN+ (in)
part D pins: 12 IN+ (in), 13 IN- (in), 14 OUT (out)

## TS274BCD
designator U?
High-Speed CMOS Quad Operational Amplifier
footprint SO14_N (SOIC, 14-Leads, Body 8.7x3.9mm, Pitch 1.27mm, IPC Medium Density)
footprint SO14_L (SOIC, 14-Leads, Body 8.7x3.9mm, Pitch 1.27mm, IPC High Density)
footprint SO14_M (SOIC, 14-Leads, Body 8.7x3.9mm, Pitch 1.27mm, IPC Low Density)
3D model SO14 (14-Pin Small Outline Integrated Circuit 1.27 mm Pitch)
pins on every part: 4 V+ (power), 11 V- (power)
part A pins: 1 OUT (out), 2 IN- (in), 3 IN+ (in)
part B pins: 5 IN+ (in), 6 IN- (in), 7 OUT (out)
part C pins: 8 OUT (out), 9 IN- (in), 10 IN+ (in)
part D pins: 12 IN+ (in), 13 IN- (in), 14 OUT (out)

## TS274BCN
designator U?
High-Speed CMOS Quad Operational Amplifier
footprint DIP14 (DIP; 14 Leads; Row Spacing 7.62 mm; Pitch 2.54 mm)
3D model DIP14 (DIP; 14 Leads; Row Spacing 7.62 mm; Pitch 2.54 mm)
pins on every part: 4 V+ (power), 11 V- (power)
part A pins: 1 OUT (out), 2 IN- (in), 3 IN+ (in)
part B pins: 5 IN+ (in), 6 IN- (in), 7 OUT (out)
part C pins: 8 OUT (out), 9 IN- (in), 10 IN+ (in)
part D pins: 12 IN+ (in), 13 IN- (in), 14 OUT (out)

## TS274BID
designator U?
High-Speed CMOS Quad Operational Amplifier
footprint SO14_N (SOIC, 14-Leads, Body 8.7x3.9mm, Pitch 1.27mm, IPC Medium Density)
footprint SO14_L (SOIC, 14-Leads, Body 8.7x3.9mm, Pitch 1.27mm, IPC High Density)
footprint SO14_M (SOIC, 14-Leads, Body 8.7x3.9mm, Pitch 1.27mm, IPC Low Density)
3D model SO14 (14-Pin Small Outline Integrated Circuit 1.27 mm Pitch)
pins on every part: 4 V+ (power), 11 V- (power)
part A pins: 1 OUT (out), 2 IN- (in), 3 IN+ (in)
part B pins: 5 IN+ (in), 6 IN- (in), 7 OUT (out)
part C pins: 8 OUT (out), 9 IN- (in), 10 IN+ (in)
part D pins: 12 IN+ (in), 13 IN- (in), 14 OUT (out)

## TS274BIN
designator U?
High-Speed CMOS Quad Operational Amplifier
footprint DIP14 (DIP; 14 Leads; Row Spacing 7.62 mm; Pitch 2.54 mm)
3D model DIP14 (DIP; 14 Leads; Row Spacing 7.62 mm; Pitch 2.54 mm)
pins on every part: 4 V+ (power), 11 V- (power)
part A pins: 1 OUT (out), 2 IN- (in), 3 IN+ (in)
part B pins: 5 IN+ (in), 6 IN- (in), 7 OUT (out)
part C pins: 8 OUT (out), 9 IN- (in), 10 IN+ (in)
part D pins: 12 IN+ (in), 13 IN- (in), 14 OUT (out)

## TS274BMD
designator U?
High-Speed CMOS Quad Operational Amplifier
footprint SO14_N (SOIC, 14-Leads, Body 8.7x3.9mm, Pitch 1.27mm, IPC Medium Density)
footprint SO14_L (SOIC, 14-Leads, Body 8.7x3.9mm, Pitch 1.27mm, IPC High Density)
footprint SO14_M (SOIC, 14-Leads, Body 8.7x3.9mm, Pitch 1.27mm, IPC Low Density)
3D model SO14 (14-Pin Small Outline Integrated Circuit 1.27 mm Pitch)
pins on every part: 4 V+ (power), 11 V- (power)
part A pins: 1 OUT (out), 2 IN- (in), 3 IN+ (in)
part B pins: 5 IN+ (in), 6 IN- (in), 7 OUT (out)
part C pins: 8 OUT (out), 9 IN- (in), 10 IN+ (in)
part D pins: 12 IN+ (in), 13 IN- (in), 14 OUT (out)

## TS274BMN
designator U?
High-Speed CMOS Quad Operational Amplifier
footprint DIP14 (DIP; 14 Leads; Row Spacing 7.62 mm; Pitch 2.54 mm)
3D model DIP14 (DIP; 14 Leads; Row Spacing 7.62 mm; Pitch 2.54 mm)
pins on every part: 4 V+ (power), 11 V- (power)
part A pins: 1 OUT (out), 2 IN- (in), 3 IN+ (in)
part B pins: 5 IN+ (in), 6 IN- (in), 7 OUT (out)
part C pins: 8 OUT (out), 9 IN- (in), 10 IN+ (in)
part D pins: 12 IN+ (in), 13 IN- (in), 14 OUT (out)

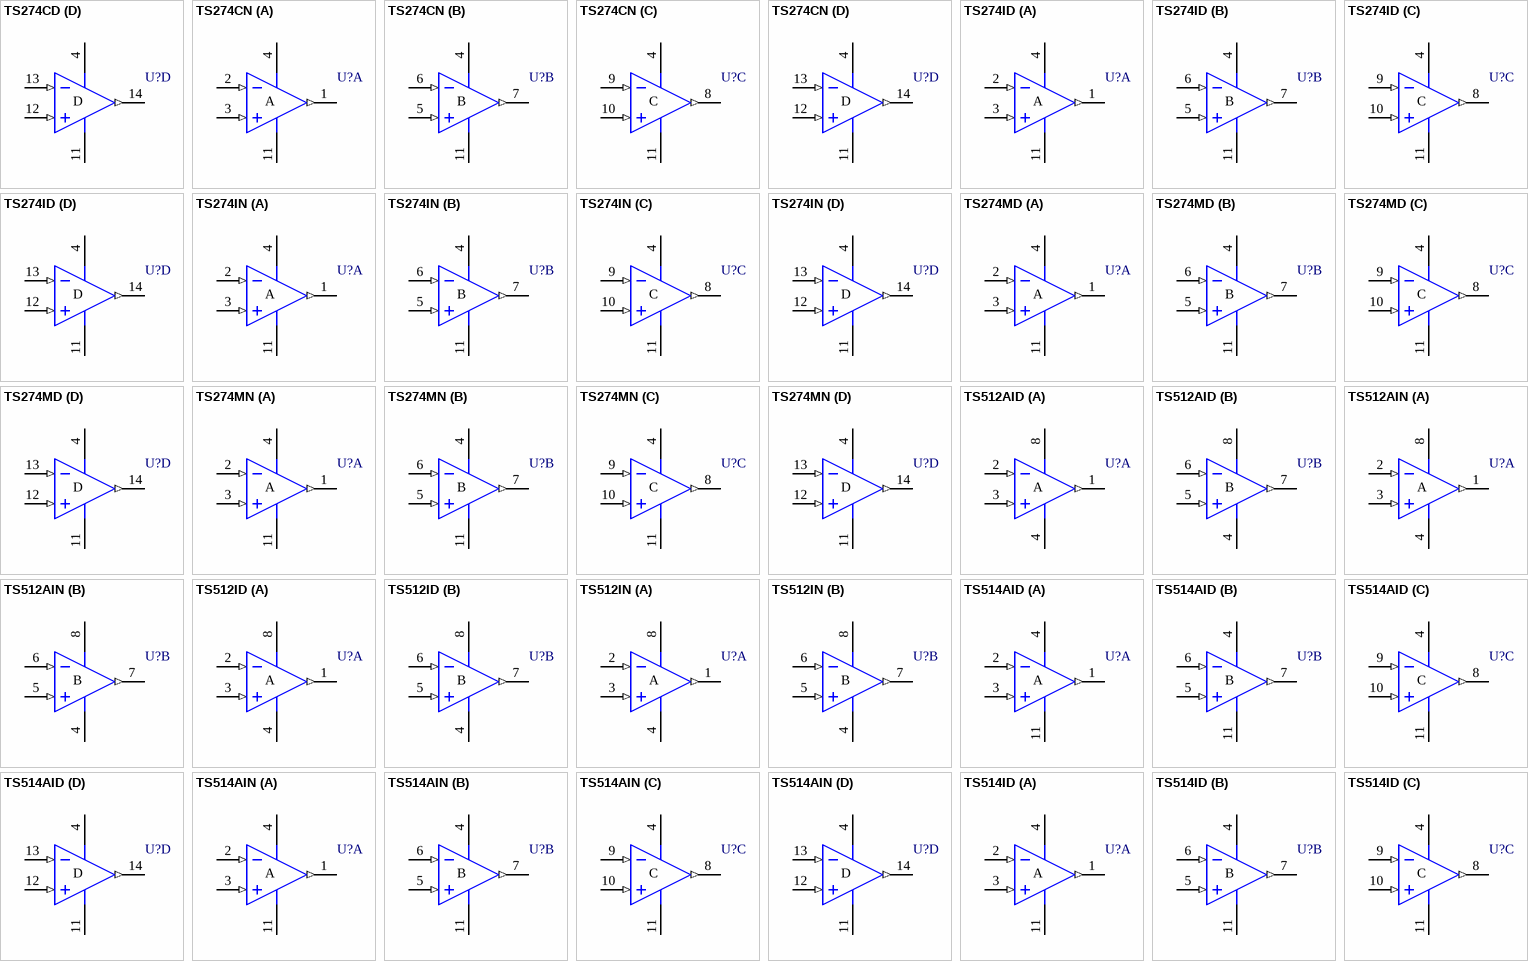
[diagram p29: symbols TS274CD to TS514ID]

## TS274CD
designator U?
High-Speed CMOS Quad Operational Amplifier
footprint SO14_N (SOIC, 14-Leads, Body 8.7x3.9mm, Pitch 1.27mm, IPC Medium Density)
footprint SO14_L (SOIC, 14-Leads, Body 8.7x3.9mm, Pitch 1.27mm, IPC High Density)
footprint SO14_M (SOIC, 14-Leads, Body 8.7x3.9mm, Pitch 1.27mm, IPC Low Density)
3D model SO14 (14-Pin Small Outline Integrated Circuit 1.27 mm Pitch)
pins on every part: 4 V+ (power), 11 V- (power)
part A pins: 1 OUT (out), 2 IN- (in), 3 IN+ (in)
part B pins: 5 IN+ (in), 6 IN- (in), 7 OUT (out)
part C pins: 8 OUT (out), 9 IN- (in), 10 IN+ (in)
part D pins: 12 IN+ (in), 13 IN- (in), 14 OUT (out)

## TS274CN
designator U?
High-Speed CMOS Quad Operational Amplifier
footprint DIP14 (DIP; 14 Leads; Row Spacing 7.62 mm; Pitch 2.54 mm)
3D model DIP14 (DIP; 14 Leads; Row Spacing 7.62 mm; Pitch 2.54 mm)
pins on every part: 4 V+ (power), 11 V- (power)
part A pins: 1 OUT (out), 2 IN- (in), 3 IN+ (in)
part B pins: 5 IN+ (in), 6 IN- (in), 7 OUT (out)
part C pins: 8 OUT (out), 9 IN- (in), 10 IN+ (in)
part D pins: 12 IN+ (in), 13 IN- (in), 14 OUT (out)

## TS274ID
designator U?
High-Speed CMOS Quad Operational Amplifier
footprint SO14_N (SOIC, 14-Leads, Body 8.7x3.9mm, Pitch 1.27mm, IPC Medium Density)
footprint SO14_L (SOIC, 14-Leads, Body 8.7x3.9mm, Pitch 1.27mm, IPC High Density)
footprint SO14_M (SOIC, 14-Leads, Body 8.7x3.9mm, Pitch 1.27mm, IPC Low Density)
3D model SO14 (14-Pin Small Outline Integrated Circuit 1.27 mm Pitch)
pins on every part: 4 V+ (power), 11 V- (power)
part A pins: 1 OUT (out), 2 IN- (in), 3 IN+ (in)
part B pins: 5 IN+ (in), 6 IN- (in), 7 OUT (out)
part C pins: 8 OUT (out), 9 IN- (in), 10 IN+ (in)
part D pins: 12 IN+ (in), 13 IN- (in), 14 OUT (out)

## TS274IN
designator U?
High-Speed CMOS Quad Operational Amplifier
footprint DIP14 (DIP; 14 Leads; Row Spacing 7.62 mm; Pitch 2.54 mm)
3D model DIP14 (DIP; 14 Leads; Row Spacing 7.62 mm; Pitch 2.54 mm)
pins on every part: 4 V+ (power), 11 V- (power)
part A pins: 1 OUT (out), 2 IN- (in), 3 IN+ (in)
part B pins: 5 IN+ (in), 6 IN- (in), 7 OUT (out)
part C pins: 8 OUT (out), 9 IN- (in), 10 IN+ (in)
part D pins: 12 IN+ (in), 13 IN- (in), 14 OUT (out)

## TS274MD
designator U?
High-Speed CMOS Quad Operational Amplifier
footprint SO14_N (SOIC, 14-Leads, Body 8.7x3.9mm, Pitch 1.27mm, IPC Medium Density)
footprint SO14_L (SOIC, 14-Leads, Body 8.7x3.9mm, Pitch 1.27mm, IPC High Density)
footprint SO14_M (SOIC, 14-Leads, Body 8.7x3.9mm, Pitch 1.27mm, IPC Low Density)
3D model SO14 (14-Pin Small Outline Integrated Circuit 1.27 mm Pitch)
pins on every part: 4 V+ (power), 11 V- (power)
part A pins: 1 OUT (out), 2 IN- (in), 3 IN+ (in)
part B pins: 5 IN+ (in), 6 IN- (in), 7 OUT (out)
part C pins: 8 OUT (out), 9 IN- (in), 10 IN+ (in)
part D pins: 12 IN+ (in), 13 IN- (in), 14 OUT (out)

## TS274MN
designator U?
High-Speed CMOS Quad Operational Amplifier
footprint DIP14 (DIP; 14 Leads; Row Spacing 7.62 mm; Pitch 2.54 mm)
3D model DIP14 (DIP; 14 Leads; Row Spacing 7.62 mm; Pitch 2.54 mm)
pins on every part: 4 V+ (power), 11 V- (power)
part A pins: 1 OUT (out), 2 IN- (in), 3 IN+ (in)
part B pins: 5 IN+ (in), 6 IN- (in), 7 OUT (out)
part C pins: 8 OUT (out), 9 IN- (in), 10 IN+ (in)
part D pins: 12 IN+ (in), 13 IN- (in), 14 OUT (out)

## TS512AID
designator U?
High-Speed Precision Dual Operational Amplifier
footprint SO8_N (SOIC, 8-Leads, Body 4.9x3.9mm, Pitch 1.27mm, IPC Medium Density)
footprint SO8_L (SOIC, 8-Leads, Body 4.9x3.9mm, Pitch 1.27mm, IPC High Density)
footprint SO8_M (SOIC, 8-Leads, Body 4.9x3.9mm, Pitch 1.27mm, IPC Low Density)
3D model SO8 (8-Pin Small Outline Integrated Circuit 1.27 mm Pitch)
pins on every part: 4 V- (power), 8 V+ (power)
part A pins: 1 OUT (out), 2 IN- (in), 3 IN+ (in)
part B pins: 5 IN+ (in), 6 IN- (in), 7 OUT (out)

## TS512AIN
designator U?
High-Speed Precision Dual Operational Amplifier
footprint DIP8 (DIP; 8 Leads; Row Spacing 7.62 mm; Pitch 2.54 mm)
3D model DIP8 (DIP; 8 Leads; Row Spacing 7.62 mm; Pitch 2.54 mm)
pins on every part: 4 V- (power), 8 V+ (power)
part A pins: 1 OUT (out), 2 IN- (in), 3 IN+ (in)
part B pins: 5 IN+ (in), 6 IN- (in), 7 OUT (out)

## TS512ID
designator U?
High-Speed Precision Dual Operational Amplifier
footprint SO8_N (SOIC, 8-Leads, Body 4.9x3.9mm, Pitch 1.27mm, IPC Medium Density)
footprint SO8_L (SOIC, 8-Leads, Body 4.9x3.9mm, Pitch 1.27mm, IPC High Density)
footprint SO8_M (SOIC, 8-Leads, Body 4.9x3.9mm, Pitch 1.27mm, IPC Low Density)
3D model SO8 (8-Pin Small Outline Integrated Circuit 1.27 mm Pitch)
pins on every part: 4 V- (power), 8 V+ (power)
part A pins: 1 OUT (out), 2 IN- (in), 3 IN+ (in)
part B pins: 5 IN+ (in), 6 IN- (in), 7 OUT (out)

## TS512IN
designator U?
High-Speed Precision Dual Operational Amplifier
footprint DIP8 (DIP; 8 Leads; Row Spacing 7.62 mm; Pitch 2.54 mm)
3D model DIP8 (DIP; 8 Leads; Row Spacing 7.62 mm; Pitch 2.54 mm)
pins on every part: 4 V- (power), 8 V+ (power)
part A pins: 1 OUT (out), 2 IN- (in), 3 IN+ (in)
part B pins: 5 IN+ (in), 6 IN- (in), 7 OUT (out)

## TS514AID
designator U?
High-Speed Precision Quad Operational Amplifier
footprint SO14_N (SOIC, 14-Leads, Body 8.7x3.9mm, Pitch 1.27mm, IPC Medium Density)
footprint SO14_L (SOIC, 14-Leads, Body 8.7x3.9mm, Pitch 1.27mm, IPC High Density)
footprint SO14_M (SOIC, 14-Leads, Body 8.7x3.9mm, Pitch 1.27mm, IPC Low Density)
3D model SO14 (14-Pin Small Outline Integrated Circuit 1.27 mm Pitch)
pins on every part: 4 V+ (power), 11 V- (power)
part A pins: 1 OUT (out), 2 IN- (in), 3 IN+ (in)
part B pins: 5 IN+ (in), 6 IN- (in), 7 OUT (out)
part C pins: 8 OUT (out), 9 IN- (in), 10 IN+ (in)
part D pins: 12 IN+ (in), 13 IN- (in), 14 OUT (out)

## TS514AIN
designator U?
High-Speed Precision Quad Operational Amplifier
footprint DIP14 (DIP; 14 Leads; Row Spacing 7.62 mm; Pitch 2.54 mm)
3D model DIP14 (DIP; 14 Leads; Row Spacing 7.62 mm; Pitch 2.54 mm)
pins on every part: 4 V+ (power), 11 V- (power)
part A pins: 1 OUT (out), 2 IN- (in), 3 IN+ (in)
part B pins: 5 IN+ (in), 6 IN- (in), 7 OUT (out)
part C pins: 8 OUT (out), 9 IN- (in), 10 IN+ (in)
part D pins: 12 IN+ (in), 13 IN- (in), 14 OUT (out)

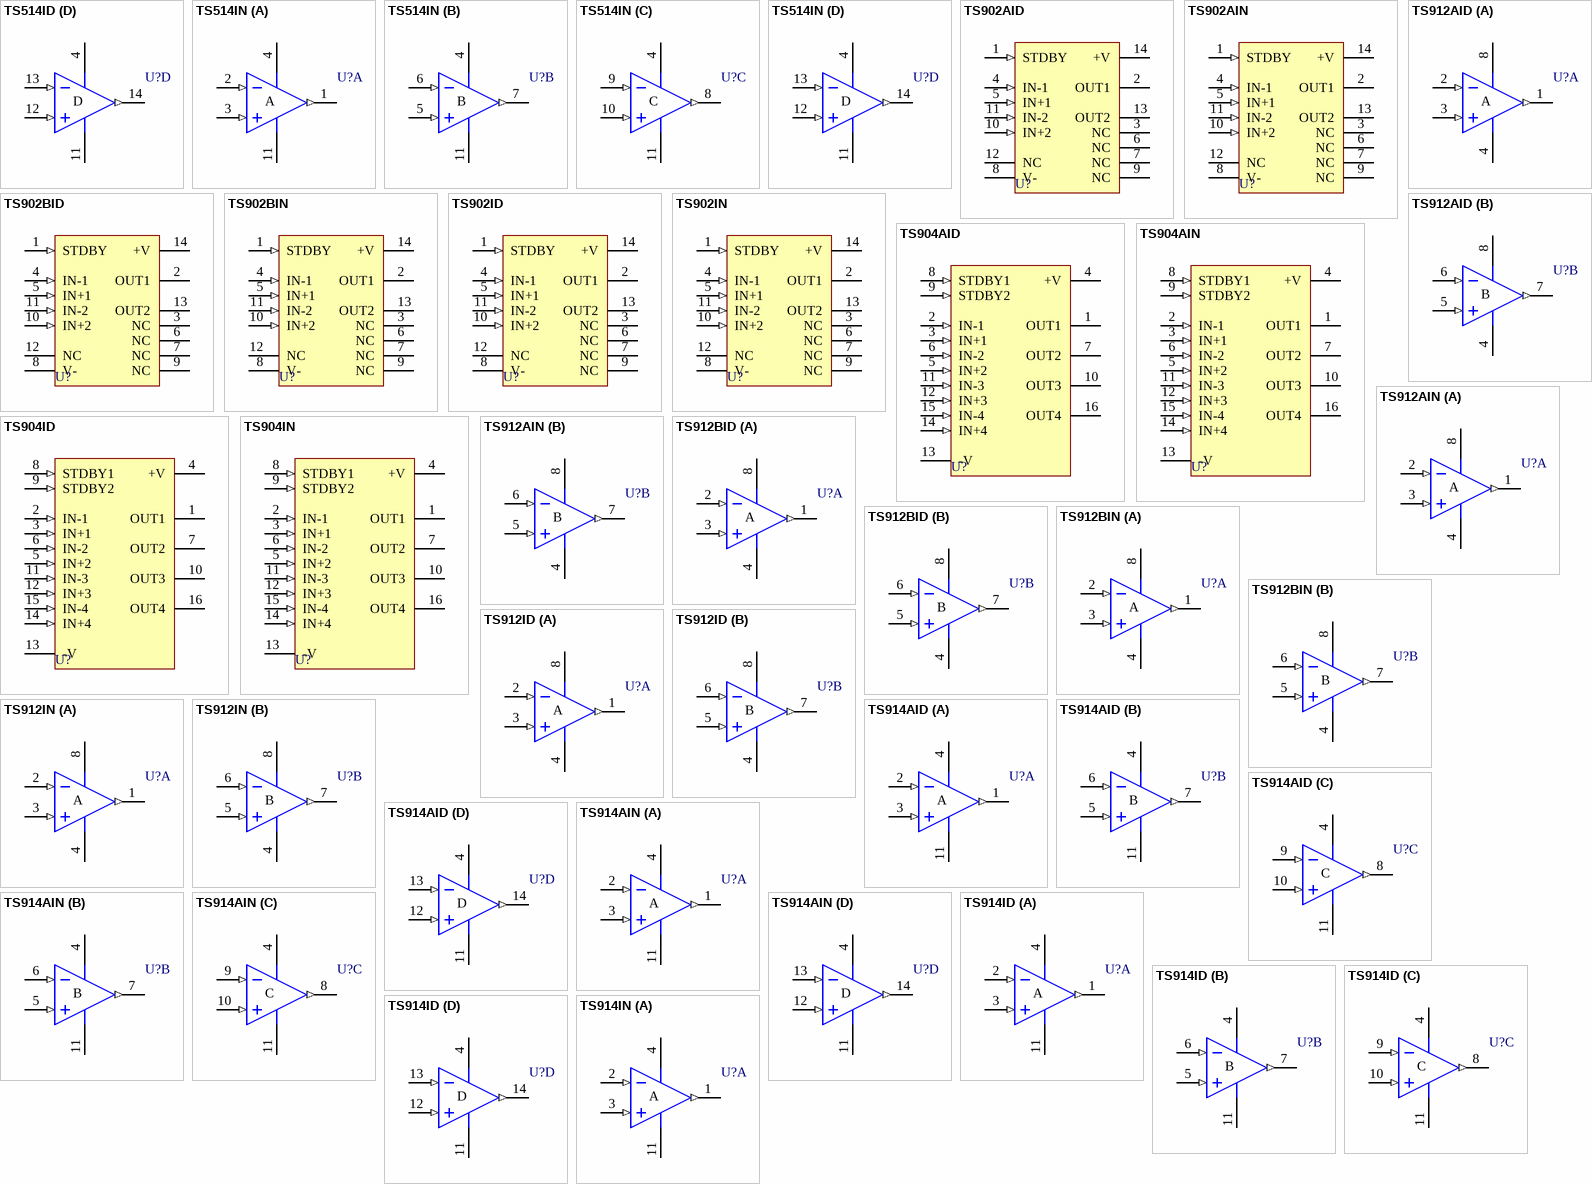
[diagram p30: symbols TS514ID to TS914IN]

## TS514ID
designator U?
High-Speed Precision Quad Operational Amplifier
footprint SO14_N (SOIC, 14-Leads, Body 8.7x3.9mm, Pitch 1.27mm, IPC Medium Density)
footprint SO14_L (SOIC, 14-Leads, Body 8.7x3.9mm, Pitch 1.27mm, IPC High Density)
footprint SO14_M (SOIC, 14-Leads, Body 8.7x3.9mm, Pitch 1.27mm, IPC Low Density)
3D model SO14 (14-Pin Small Outline Integrated Circuit 1.27 mm Pitch)
pins on every part: 4 V+ (power), 11 V- (power)
part A pins: 1 OUT (out), 2 IN- (in), 3 IN+ (in)
part B pins: 5 IN+ (in), 6 IN- (in), 7 OUT (out)
part C pins: 8 OUT (out), 9 IN- (in), 10 IN+ (in)
part D pins: 12 IN+ (in), 13 IN- (in), 14 OUT (out)

## TS514IN
designator U?
High-Speed Precision Quad Operational Amplifier
footprint DIP14 (DIP; 14 Leads; Row Spacing 7.62 mm; Pitch 2.54 mm)
3D model DIP14 (DIP; 14 Leads; Row Spacing 7.62 mm; Pitch 2.54 mm)
pins on every part: 4 V+ (power), 11 V- (power)
part A pins: 1 OUT (out), 2 IN- (in), 3 IN+ (in)
part B pins: 5 IN+ (in), 6 IN- (in), 7 OUT (out)
part C pins: 8 OUT (out), 9 IN- (in), 10 IN+ (in)
part D pins: 12 IN+ (in), 13 IN- (in), 14 OUT (out)

## TS902AID
designator U?
Rail-to-Rail CMOS Dual Operational Amplifier (with Standby Position)
footprint SO14_N (SOIC, 14-Leads, Body 8.7x3.9mm, Pitch 1.27mm, IPC Medium Density)
footprint SO14_L (SOIC, 14-Leads, Body 8.7x3.9mm, Pitch 1.27mm, IPC High Density)
footprint SO14_M (SOIC, 14-Leads, Body 8.7x3.9mm, Pitch 1.27mm, IPC Low Density)
3D model SO14 (14-Pin Small Outline Integrated Circuit 1.27 mm Pitch)
pins: 1 STDBY (in), 2 OUT1 (hiz), 3 NC, 4 IN-1 (in), 5 IN+1 (in), 6 NC, 7 NC, 8 V- (power), 9 NC, 10 IN+2 (in), 11 IN-2 (in), 12 NC, 13 OUT2 (hiz), 14 +V (power)

## TS902AIN
designator U?
Rail-to-Rail CMOS Dual Operational Amplifier (with Standby Position)
footprint DIP14 (DIP; 14 Leads; Row Spacing 7.62 mm; Pitch 2.54 mm)
3D model DIP14 (DIP; 14 Leads; Row Spacing 7.62 mm; Pitch 2.54 mm)
pins: 1 STDBY (in), 2 OUT1 (hiz), 3 NC, 4 IN-1 (in), 5 IN+1 (in), 6 NC, 7 NC, 8 V- (power), 9 NC, 10 IN+2 (in), 11 IN-2 (in), 12 NC, 13 OUT2 (hiz), 14 +V (power)

## TS902BID
designator U?
Rail-to-Rail CMOS Dual Operational Amplifier (with Standby Position)
footprint SO14_N (SOIC, 14-Leads, Body 8.7x3.9mm, Pitch 1.27mm, IPC Medium Density)
footprint SO14_L (SOIC, 14-Leads, Body 8.7x3.9mm, Pitch 1.27mm, IPC High Density)
footprint SO14_M (SOIC, 14-Leads, Body 8.7x3.9mm, Pitch 1.27mm, IPC Low Density)
3D model SO14 (14-Pin Small Outline Integrated Circuit 1.27 mm Pitch)
pins: 1 STDBY (in), 2 OUT1 (hiz), 3 NC, 4 IN-1 (in), 5 IN+1 (in), 6 NC, 7 NC, 8 V- (power), 9 NC, 10 IN+2 (in), 11 IN-2 (in), 12 NC, 13 OUT2 (hiz), 14 +V (power)

## TS902BIN
designator U?
Rail-to-Rail CMOS Dual Operational Amplifier (with Standby Position)
footprint DIP14 (DIP; 14 Leads; Row Spacing 7.62 mm; Pitch 2.54 mm)
3D model DIP14 (DIP; 14 Leads; Row Spacing 7.62 mm; Pitch 2.54 mm)
pins: 1 STDBY (in), 2 OUT1 (hiz), 3 NC, 4 IN-1 (in), 5 IN+1 (in), 6 NC, 7 NC, 8 V- (power), 9 NC, 10 IN+2 (in), 11 IN-2 (in), 12 NC, 13 OUT2 (hiz), 14 +V (power)

## TS902ID
designator U?
Rail-to-Rail CMOS Dual Operational Amplifier (with Standby Position)
footprint SO14_N (SOIC, 14-Leads, Body 8.7x3.9mm, Pitch 1.27mm, IPC Medium Density)
footprint SO14_L (SOIC, 14-Leads, Body 8.7x3.9mm, Pitch 1.27mm, IPC High Density)
footprint SO14_M (SOIC, 14-Leads, Body 8.7x3.9mm, Pitch 1.27mm, IPC Low Density)
3D model SO14 (14-Pin Small Outline Integrated Circuit 1.27 mm Pitch)
pins: 1 STDBY (in), 2 OUT1 (hiz), 3 NC, 4 IN-1 (in), 5 IN+1 (in), 6 NC, 7 NC, 8 V- (power), 9 NC, 10 IN+2 (in), 11 IN-2 (in), 12 NC, 13 OUT2 (hiz), 14 +V (power)

## TS902IN
designator U?
Rail-to-Rail CMOS Dual Operational Amplifier (with Standby Position)
footprint DIP14 (DIP; 14 Leads; Row Spacing 7.62 mm; Pitch 2.54 mm)
3D model DIP14 (DIP; 14 Leads; Row Spacing 7.62 mm; Pitch 2.54 mm)
pins: 1 STDBY (in), 2 OUT1 (hiz), 3 NC, 4 IN-1 (in), 5 IN+1 (in), 6 NC, 7 NC, 8 V- (power), 9 NC, 10 IN+2 (in), 11 IN-2 (in), 12 NC, 13 OUT2 (hiz), 14 +V (power)

## TS904AID
designator U?
Rail-to-Rail CMOS Quad Operational Amplifier (with Standby Position)
footprint SO16_N (SOIC, 16-Leads, Body 9.9x3.9mm, Pitch 1.27mm, IPC Medium Density)
footprint SO16_L (SOIC, 16-Leads, Body 9.9x3.9mm, Pitch 1.27mm, IPC High Density)
footprint SO16_M (SOIC, 16-Leads, Body 9.9x3.9mm, Pitch 1.27mm, IPC Low Density)
3D model SO16 (16-Pin Small Outline Integrated Circuit 1.27 mm Pitch)
pins: 1 OUT1 (hiz), 2 IN-1 (in), 3 IN+1 (in), 4 +V (power), 5 IN+2 (in), 6 IN-2 (in), 7 OUT2 (hiz), 8 STDBY1 (in), 9 STDBY2 (in), 10 OUT3 (hiz), 11 IN-3 (in), 12 IN+3 (in), 13 -V (power), 14 IN+4 (in), 15 IN-4 (in), 16 OUT4 (hiz)

## TS904AIN
designator U?
Rail-to-Rail CMOS Quad Operational Amplifier (with Standby Position)
footprint DIP16 (DIP; 16 Leads; Row Spacing 7.62 mm; Pitch 2.54 mm)
3D model DIP16 (DIP; 16 Leads; Row Spacing 7.62 mm; Pitch 2.54 mm)
pins: 1 OUT1 (hiz), 2 IN-1 (in), 3 IN+1 (in), 4 +V (power), 5 IN+2 (in), 6 IN-2 (in), 7 OUT2 (hiz), 8 STDBY1 (in), 9 STDBY2 (in), 10 OUT3 (hiz), 11 IN-3 (in), 12 IN+3 (in), 13 -V (power), 14 IN+4 (in), 15 IN-4 (in), 16 OUT4 (hiz)

## TS904ID
designator U?
Rail-to-Rail CMOS Quad Operational Amplifier (with Standby Position)
footprint SO16_N (SOIC, 16-Leads, Body 9.9x3.9mm, Pitch 1.27mm, IPC Medium Density)
footprint SO16_L (SOIC, 16-Leads, Body 9.9x3.9mm, Pitch 1.27mm, IPC High Density)
footprint SO16_M (SOIC, 16-Leads, Body 9.9x3.9mm, Pitch 1.27mm, IPC Low Density)
3D model SO16 (16-Pin Small Outline Integrated Circuit 1.27 mm Pitch)
pins: 1 OUT1 (hiz), 2 IN-1 (in), 3 IN+1 (in), 4 +V (power), 5 IN+2 (in), 6 IN-2 (in), 7 OUT2 (hiz), 8 STDBY1 (in), 9 STDBY2 (in), 10 OUT3 (hiz), 11 IN-3 (in), 12 IN+3 (in), 13 -V (power), 14 IN+4 (in), 15 IN-4 (in), 16 OUT4 (hiz)

## TS904IN
designator U?
Rail-to-Rail CMOS Quad Operational Amplifier (with Standby Position)
footprint DIP16 (DIP; 16 Leads; Row Spacing 7.62 mm; Pitch 2.54 mm)
3D model DIP16 (DIP; 16 Leads; Row Spacing 7.62 mm; Pitch 2.54 mm)
pins: 1 OUT1 (hiz), 2 IN-1 (in), 3 IN+1 (in), 4 +V (power), 5 IN+2 (in), 6 IN-2 (in), 7 OUT2 (hiz), 8 STDBY1 (in), 9 STDBY2 (in), 10 OUT3 (hiz), 11 IN-3 (in), 12 IN+3 (in), 13 -V (power), 14 IN+4 (in), 15 IN-4 (in), 16 OUT4 (hiz)

## TS912AID
designator U?
Rail-to-Rail CMOS Dual Operational Amplifier
footprint SO8_N (SOIC, 8-Leads, Body 4.9x3.9mm, Pitch 1.27mm, IPC Medium Density)
footprint SO8_L (SOIC, 8-Leads, Body 4.9x3.9mm, Pitch 1.27mm, IPC High Density)
footprint SO8_M (SOIC, 8-Leads, Body 4.9x3.9mm, Pitch 1.27mm, IPC Low Density)
3D model SO8 (8-Pin Small Outline Integrated Circuit 1.27 mm Pitch)
pins on every part: 4 V- (power), 8 V+ (power)
part A pins: 1 OUT (out), 2 IN- (in), 3 IN+ (in)
part B pins: 5 IN+ (in), 6 IN- (in), 7 OUT (out)

## TS912AIN
designator U?
Rail-to-Rail CMOS Dual Operational Amplifier
footprint DIP8 (DIP; 8 Leads; Row Spacing 7.62 mm; Pitch 2.54 mm)
3D model DIP8 (DIP; 8 Leads; Row Spacing 7.62 mm; Pitch 2.54 mm)
pins on every part: 4 V- (power), 8 V+ (power)
part A pins: 1 OUT (out), 2 IN- (in), 3 IN+ (in)
part B pins: 5 IN+ (in), 6 IN- (in), 7 OUT (out)

## TS912BID
designator U?
Rail-to-Rail CMOS Dual Operational Amplifier
footprint SO8_N (SOIC, 8-Leads, Body 4.9x3.9mm, Pitch 1.27mm, IPC Medium Density)
footprint SO8_L (SOIC, 8-Leads, Body 4.9x3.9mm, Pitch 1.27mm, IPC High Density)
footprint SO8_M (SOIC, 8-Leads, Body 4.9x3.9mm, Pitch 1.27mm, IPC Low Density)
3D model SO8 (8-Pin Small Outline Integrated Circuit 1.27 mm Pitch)
pins on every part: 4 V- (power), 8 V+ (power)
part A pins: 1 OUT (out), 2 IN- (in), 3 IN+ (in)
part B pins: 5 IN+ (in), 6 IN- (in), 7 OUT (out)

## TS912BIN
designator U?
Rail-to-Rail CMOS Dual Operational Amplifier
footprint DIP8 (DIP; 8 Leads; Row Spacing 7.62 mm; Pitch 2.54 mm)
3D model DIP8 (DIP; 8 Leads; Row Spacing 7.62 mm; Pitch 2.54 mm)
pins on every part: 4 V- (power), 8 V+ (power)
part A pins: 1 OUT (out), 2 IN- (in), 3 IN+ (in)
part B pins: 5 IN+ (in), 6 IN- (in), 7 OUT (out)

## TS912ID
designator U?
Rail-to-Rail CMOS Dual Operational Amplifier
footprint SO8_N (SOIC, 8-Leads, Body 4.9x3.9mm, Pitch 1.27mm, IPC Medium Density)
footprint SO8_L (SOIC, 8-Leads, Body 4.9x3.9mm, Pitch 1.27mm, IPC High Density)
footprint SO8_M (SOIC, 8-Leads, Body 4.9x3.9mm, Pitch 1.27mm, IPC Low Density)
3D model SO8 (8-Pin Small Outline Integrated Circuit 1.27 mm Pitch)
pins on every part: 4 V- (power), 8 V+ (power)
part A pins: 1 OUT (out), 2 IN- (in), 3 IN+ (in)
part B pins: 5 IN+ (in), 6 IN- (in), 7 OUT (out)

## TS912IN
designator U?
Rail-to-Rail CMOS Dual Operational Amplifier
footprint DIP8 (DIP; 8 Leads; Row Spacing 7.62 mm; Pitch 2.54 mm)
3D model DIP8 (DIP; 8 Leads; Row Spacing 7.62 mm; Pitch 2.54 mm)
pins on every part: 4 V- (power), 8 V+ (power)
part A pins: 1 OUT (out), 2 IN- (in), 3 IN+ (in)
part B pins: 5 IN+ (in), 6 IN- (in), 7 OUT (out)

## TS914AID
designator U?
Rail-to-Rail CMOS Quad Operational Amplifier
footprint SO14_N (SOIC, 14-Leads, Body 8.7x3.9mm, Pitch 1.27mm, IPC Medium Density)
footprint SO14_L (SOIC, 14-Leads, Body 8.7x3.9mm, Pitch 1.27mm, IPC High Density)
footprint SO14_M (SOIC, 14-Leads, Body 8.7x3.9mm, Pitch 1.27mm, IPC Low Density)
3D model SO14 (14-Pin Small Outline Integrated Circuit 1.27 mm Pitch)
pins on every part: 4 V+ (power), 11 V- (power)
part A pins: 1 OUT (out), 2 IN- (in), 3 IN+ (in)
part B pins: 5 IN+ (in), 6 IN- (in), 7 OUT (out)
part C pins: 8 OUT (out), 9 IN- (in), 10 IN+ (in)
part D pins: 12 IN+ (in), 13 IN- (in), 14 OUT (out)

## TS914AIN
designator U?
Rail-to-Rail CMOS Quad Operational Amplifier
footprint DIP14 (DIP; 14 Leads; Row Spacing 7.62 mm; Pitch 2.54 mm)
3D model DIP14 (DIP; 14 Leads; Row Spacing 7.62 mm; Pitch 2.54 mm)
pins on every part: 4 V+ (power), 11 V- (power)
part A pins: 1 OUT (out), 2 IN- (in), 3 IN+ (in)
part B pins: 5 IN+ (in), 6 IN- (in), 7 OUT (out)
part C pins: 8 OUT (out), 9 IN- (in), 10 IN+ (in)
part D pins: 12 IN+ (in), 13 IN- (in), 14 OUT (out)

## TS914ID
designator U?
Rail-to-Rail CMOS Quad Operational Amplifier
footprint SO14_N (SOIC, 14-Leads, Body 8.7x3.9mm, Pitch 1.27mm, IPC Medium Density)
footprint SO14_L (SOIC, 14-Leads, Body 8.7x3.9mm, Pitch 1.27mm, IPC High Density)
footprint SO14_M (SOIC, 14-Leads, Body 8.7x3.9mm, Pitch 1.27mm, IPC Low Density)
3D model SO14 (14-Pin Small Outline Integrated Circuit 1.27 mm Pitch)
pins on every part: 4 V+ (power), 11 V- (power)
part A pins: 1 OUT (out), 2 IN- (in), 3 IN+ (in)
part B pins: 5 IN+ (in), 6 IN- (in), 7 OUT (out)
part C pins: 8 OUT (out), 9 IN- (in), 10 IN+ (in)
part D pins: 12 IN+ (in), 13 IN- (in), 14 OUT (out)

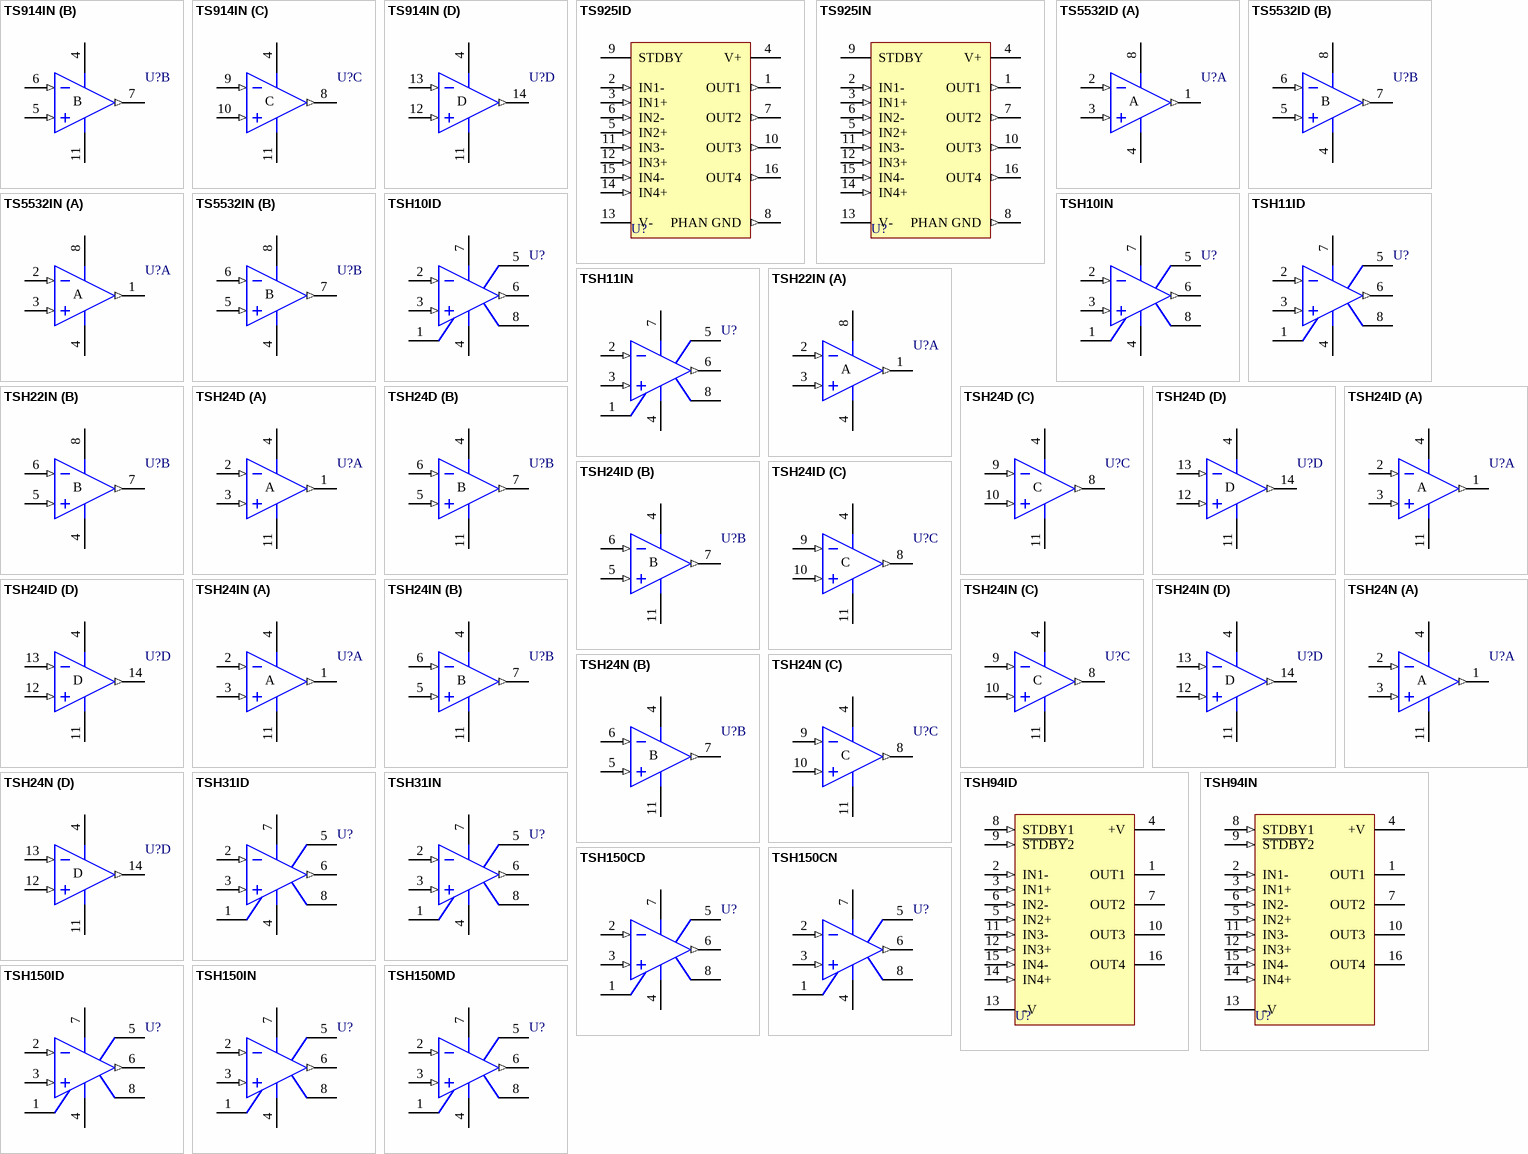
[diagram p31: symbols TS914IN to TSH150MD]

## TS914IN
designator U?
Rail-to-Rail CMOS Quad Operational Amplifier
footprint DIP14 (DIP; 14 Leads; Row Spacing 7.62 mm; Pitch 2.54 mm)
3D model DIP14 (DIP; 14 Leads; Row Spacing 7.62 mm; Pitch 2.54 mm)
pins on every part: 4 V+ (power), 11 V- (power)
part A pins: 1 OUT (out), 2 IN- (in), 3 IN+ (in)
part B pins: 5 IN+ (in), 6 IN- (in), 7 OUT (out)
part C pins: 8 OUT (out), 9 IN- (in), 10 IN+ (in)
part D pins: 12 IN+ (in), 13 IN- (in), 14 OUT (out)

## TS925ID
designator U?
Rail-to-Rail High-Output-Current Quad Operational Amplifier
footprint SO16_N (SOIC, 16-Leads, Body 9.9x3.9mm, Pitch 1.27mm, IPC Medium Density)
footprint SO16_L (SOIC, 16-Leads, Body 9.9x3.9mm, Pitch 1.27mm, IPC High Density)
footprint SO16_M (SOIC, 16-Leads, Body 9.9x3.9mm, Pitch 1.27mm, IPC Low Density)
3D model SO16 (16-Pin Small Outline Integrated Circuit 1.27 mm Pitch)
pins: 1 OUT1 (out), 2 IN1- (in), 3 IN1+ (in), 4 V+ (power), 5 IN2+ (in), 6 IN2- (in), 7 OUT2 (out), 8 PHAN GND (out), 9 STDBY, 10 OUT3 (out), 11 IN3- (in), 12 IN3+ (in), 13 V- (power), 14 IN4+ (in), 15 IN4- (in), 16 OUT4 (out)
